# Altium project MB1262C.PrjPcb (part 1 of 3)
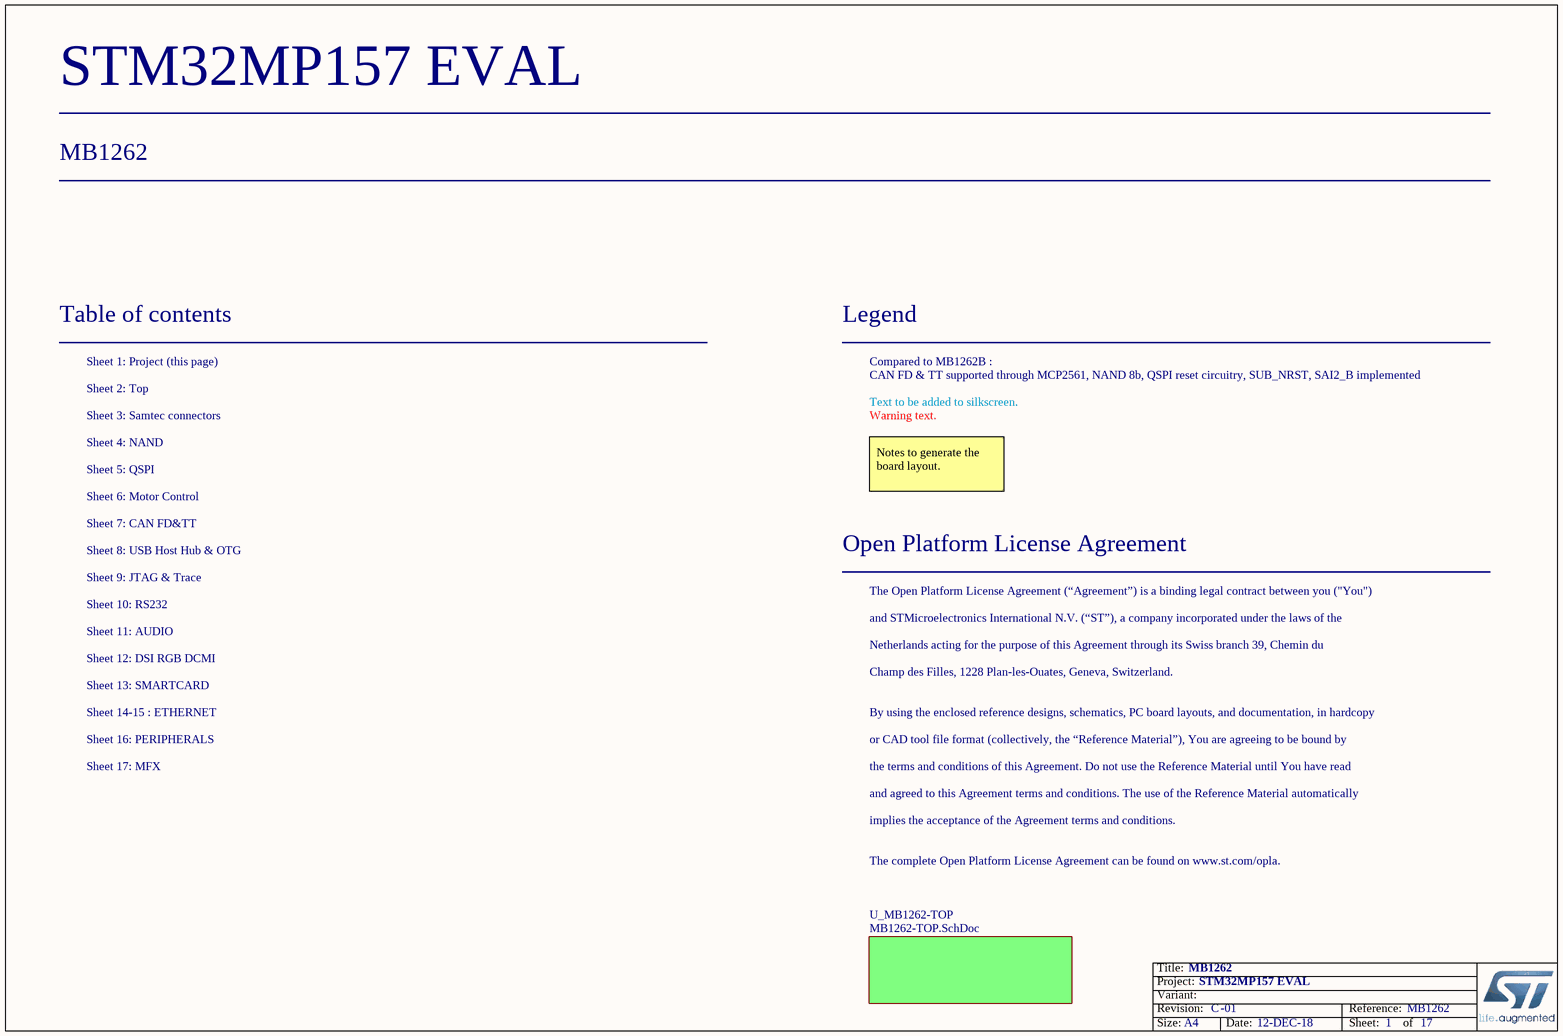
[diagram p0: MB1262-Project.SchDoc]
Board_Reference: MB1262; Board_PCB_Revision: C; Board_Name: STM32MP157 EVAL; Board_Document_Date: 12-DEC-18; Board_Assembly_Revision: 01
17 sheets, 493 parts. Net scope: hierarchical (ports join the sheet entries above them; power ports are global).
Board file: MB1262C.PcbDoc
Sheets:
  MB1262-Project.SchDoc
    U_MB1262-TOP = MB1262-TOP.SchDoc
      U_NAND = NAND.SchDoc
      U_Audio = Audio.SchDoc
      U_Ethernet = Ethernet.SchDoc
        U_Ethernet_connector = Ethernet_connector.SchDoc
      U_DSI&TFT-LCD&Camera = DSI&TFT-LCD&Camera.SchDoc
      U_Peripherals = Peripherals.SchDoc
      U_RS232 = RS232.SchDoc
      U_MotorControl = MotorControl.SchDoc
      U_CAN_FD&TT = CAN_FD&TT.SchDoc
      U_JTAG&Trace = JTAG&Trace.SchDoc
      U_QSPI = QSPI.SchDoc
      U_MFX = MFX.SchDoc
      U_Samtec Connectors QSH_North_South = Samtec Connectors QSH_North_South.SchDoc
      U_SmartCard = SmartCard.SchDoc
      U_USB_Host_Hub&OTG = USB_Host_Hub&OTG.SchDoc

## Sheet MB1262-Project.SchDoc: MB1262
size A4; Date: Not used; ApprovedBy: Not used; CheckedBy: Not used; Author: Not used; CompanyName: STMicroelectronics; DrawnBy: Not used; Engineer: Not used; Organization: Not used; Address1: Not used; Address2: Not used; Address3: Not used; Address4: Not used; DocumentNumber: Not used; Revision: Not used; SheetNumber: 1; SheetTotal: 17

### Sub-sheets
U_MB1262-TOP = MB1262-TOP.SchDoc: no entries

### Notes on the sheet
- Table of contents
- Sheet 1: Project (this page)
- Legend
- Compared to MB1262B :
- CAN FD & TT supported through MCP2561, NAND 8b, QSPI reset circuitry, SUB_NRST, SAI2_B implemented
- Sheet 2: Top
- Sheet 3: Samtec connectors
- Sheet 4: NAND
- Text to be added to silkscreen.
- Warning text.
- Sheet 6: Motor Control
- Sheet 5: QSPI
- Notes to generate the board layout.
- Sheet 7: CAN FD&TT
- Sheet 9: JTAG & Trace
- Sheet 8: USB Host Hub & OTG
- Open Platform License Agreement
- Sheet 10: RS232
- Sheet 11: AUDIO
- The Open Platform License Agreement (“Agreement”) is a binding legal contract between you ("You")
- and STMicroelectronics International N.V. (“ST”), a company incorporated under the laws of the
- Netherlands acting for the purpose of this Agreement through its Swiss branch 39, Chemin du
- Sheet 12: DSI RGB DCMI
- Sheet 13: SMARTCARD
- Sheet 14-15 : ETHERNET
- Champ des Filles, 1228 Plan-les-Ouates, Geneva, Switzerland.
- By using the enclosed reference designs, schematics, PC board layouts, and documentation, in hardcopy
- Sheet 16: PERIPHERALS
- Sheet 17: MFX
- or CAD tool file format (collectively, the “Reference Material”), You are agreeing to be bound by
- the terms and conditions of this Agreement. Do not use the Reference Material until You have read
- and agreed to this Agreement terms and conditions. The use of the Reference Material automatically
- implies the acceptance of the Agreement terms and conditions.
- The complete Open Platform License Agreement can be found on www.st.com/opla.

## Sheet MB1262-TOP.SchDoc: MB1262-TOP
size A3; DocumentNumber: MB1262; Revision: C-01; SheetNumber: 2; SheetTotal: 17; Project: STM32MP15x-EVAL; PageSetup: Record=PageOptions¦CenterHorizontal=True¦CenterVertical=True¦PrintScale=1.01¦XCorrection=1.00¦YCorrection=1.00¦PrintKind=1¦BorderSize=5000000¦LeftOffset=0¦BottomOffset=0¦Orientation=2¦PaperLength=1000¦PaperWidth=1000¦Scale=100¦PaperSource=15¦PrintQuality=600¦MediaType=1¦DitherType=10¦PrintScaleMode=1¦PaperKind=A3¦PaperIndex=8
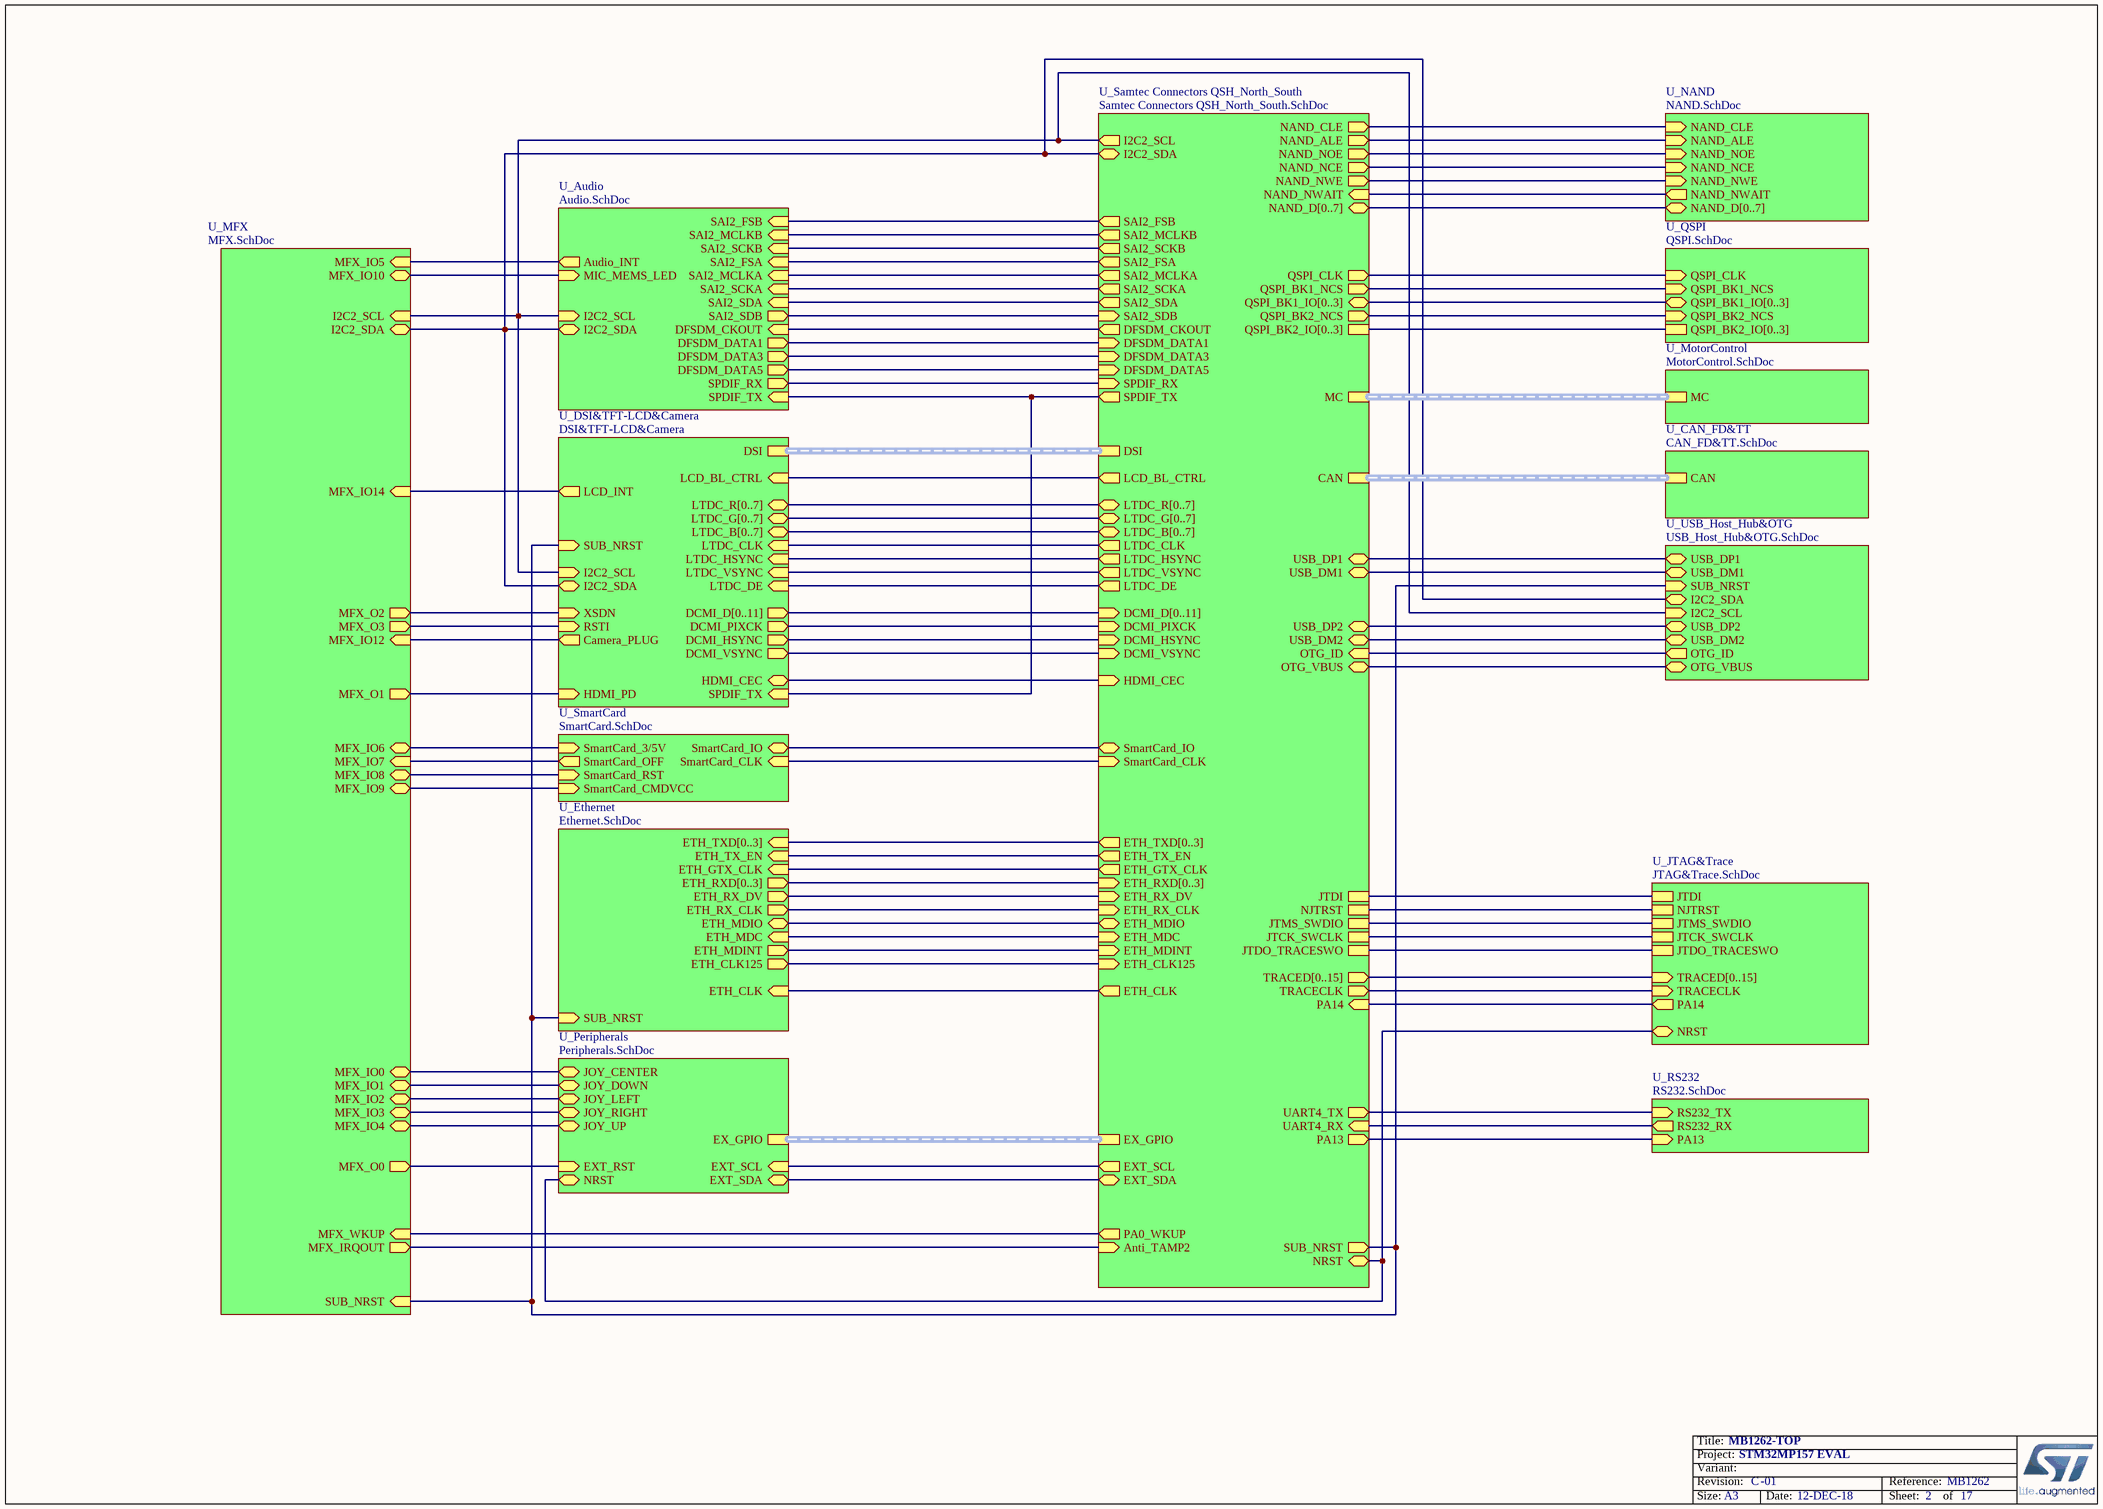
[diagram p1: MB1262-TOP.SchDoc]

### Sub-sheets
U_Audio = Audio.SchDoc: SAI2_SCKA (in), SAI2_FSA (in), SAI2_SDA (in), SAI2_SDB (out), Audio_INT (out), I2C2_SDA (bidir), I2C2_SCL (in), SAI2_MCLKA (in), DFSDM_CKOUT (in), SPDIF_RX (out), SPDIF_TX (in), DFSDM_DATA3 (out), DFSDM_DATA1 (out), DFSDM_DATA5 (out), MIC_MEMS_LED (in), SAI2_MCLKB (in), SAI2_FSB (in), SAI2_SCKB (in)
U_CAN_FD&TT = CAN_FD&TT.SchDoc: CAN (harness CAN)
U_DSI&TFT-LCD&Camera = DSI&TFT-LCD&Camera: LTDC_R[0..7] (bidir), LTDC_HSYNC (in), LTDC_VSYNC (in), LTDC_CLK (in), LTDC_B[0..7] (bidir), LTDC_G[0..7] (bidir), RSTI (in), XSDN (in), DCMI_HSYNC (out), DCMI_PIXCK (out), DCMI_VSYNC (out), Camera_PLUG (out), LCD_INT (out), LCD_BL_CTRL (in), DSI (harness DSI), HDMI_CEC (bidir), LTDC_DE (in), SUB_NRST (in), SPDIF_TX (in), DCMI_D[0..11] (out), I2C2_SDA (bidir), I2C2_SCL (in), HDMI_PD (in)
U_Ethernet = Ethernet.SchDoc: ETH_TXD[0..3] (in), ETH_TX_EN (in), ETH_GTX_CLK (in), ETH_RXD[0..3] (out), ETH_RX_DV (out), ETH_RX_CLK (out), ETH_MDIO (bidir), ETH_MDC (in), ETH_MDINT (out), ETH_CLK125 (out), SUB_NRST (in), ETH_CLK (in)
U_JTAG&Trace = JTAG&Trace.SchDoc: JTDI, NRST (bidir), TRACECLK (in), NJTRST, JTMS_SWDIO, JTCK_SWCLK, JTDO_TRACESWO, PA14 (out), TRACED[0..15] (in)
U_MFX = MFX.SchDoc: MFX_IRQOUT (out), I2C2_SCL (in), I2C2_SDA (bidir), MFX_IO5 (in), MFX_IO6 (bidir), MFX_IO7 (in), MFX_IO8 (bidir), MFX_IO9 (bidir), MFX_IO10 (bidir), MFX_IO12 (in), MFX_IO14 (in), MFX_WKUP (in), MFX_IO0 (bidir), MFX_IO1 (bidir), MFX_IO2 (bidir), MFX_IO3 (bidir), MFX_IO4 (bidir), SUB_NRST (in), MFX_O2 (out), MFX_O0 (out), MFX_O3 (out), MFX_O1 (out)
U_MotorControl = MotorControl.SchDoc: MC (harness Motor Control)
U_NAND = NAND.SchDoc: NAND_CLE (in), NAND_ALE (in), NAND_NOE (in), NAND_NCE (in), NAND_NWE (in), NAND_NWAIT (out), NAND_D[0..7] (bidir)
U_Peripherals = Peripherals.SchDoc: NRST (bidir), JOY_CENTER (bidir), JOY_DOWN (bidir), JOY_LEFT (bidir), JOY_RIGHT (bidir), JOY_UP (bidir), EXT_SCL (in), EXT_SDA (bidir), EXT_RST (in), EX_GPIO (harness EXP_GPIO)
U_QSPI = QSPI.SchDoc: QSPI_BK1_NCS (in), QSPI_CLK (in), QSPI_BK1_IO[0..3] (bidir), QSPI_BK2_NCS (in), QSPI_BK2_IO[0..3]
U_RS232 = RS232.SchDoc: RS232_TX (in), RS232_RX (out), PA13 (in)
U_Samtec Connectors QSH_North_South = Samtec Connectors QSH_North_South.SchDoc: HDMI_CEC (in), DSI (harness DSI), SPDIF_RX (in), JTMS_SWDIO, Anti_TAMP2 (in), SPDIF_TX (out), LCD_BL_CTRL (out), UART4_TX (out), UART4_RX (in), USB_DM2 (bidir), USB_DP2 (bidir), USB_DP1 (bidir), USB_DM1 (bidir), OTG_ID (in), OTG_VBUS (bidir), SAI2_MCLKA (out), SAI2_SCKA (out), SAI2_FSA (out), SAI2_SDA (out), SAI2_SDB (in), DFSDM_CKOUT (out), DFSDM_DATA1 (in), DFSDM_DATA3 (in), QSPI_CLK (out), QSPI_BK1_NCS (out), QSPI_BK1_IO[0..3] (bidir), QSPI_BK2_NCS (out), QSPI_BK2_IO[0..3], ETH_RXD[0..3] (in), ETH_RX_DV (in), ETH_TX_EN (out), ETH_GTX_CLK (out), ETH_RX_CLK (in), ETH_MDIO (bidir), ETH_MDC (in), ETH_TXD[0..3] (out), ETH_CLK125 (in), ETH_MDINT (in), SmartCard_IO (bidir), SmartCard_CLK (in), NAND_CLE (out), NAND_ALE (out), NAND_NCE (out), NAND_NOE (out), NAND_NWE (out), NAND_NWAIT (in), NAND_D[0..7] (bidir), LTDC_R[0..7] (bidir), LTDC_G[0..7] (bidir), LTDC_B[0..7] (bidir), LTDC_HSYNC (out), LTDC_VSYNC (out), LTDC_CLK (out), LTDC_DE (out), DCMI_D[0..11] (in), DCMI_VSYNC (in), DCMI_HSYNC (in), DCMI_PIXCK (in), EX_GPIO (harness EXP_GPIO), I2C2_SCL (out), I2C2_SDA (bidir), EXT_SDA (bidir), EXT_SCL (out), MC (harness Motor Control), JTCK_SWCLK, JTDI, NJTRST, JTDO_TRACESWO, NRST (bidir), PA0_WKUP (out), CAN (harness CAN), PA13 (out), PA14 (in), ETH_CLK (out), TRACED[0..15] (out), TRACECLK (out), DFSDM_DATA5 (in), SAI2_MCLKB (out), SUB_NRST (out), SAI2_SCKB (out), SAI2_FSB (out)
U_SmartCard = SmartCard.SchDoc: SmartCard_3/5V (in), SmartCard_IO (bidir), SmartCard_RST (in), SmartCard_CLK (in), SmartCard_OFF (out), SmartCard_CMDVCC (in)
U_USB_Host_Hub&OTG = USB_Host_Hub&OTG.SchDoc: USB_DP1 (bidir), USB_DM1 (bidir), SUB_NRST (in), I2C2_SDA (bidir), I2C2_SCL (in), USB_DM2 (bidir), USB_DP2 (bidir), OTG_ID (out), OTG_VBUS (bidir)

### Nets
Anti_TAMP2: sheet U_MFX/MFX_IRQOUT, sheet U_Samtec Connectors QSH_North_South/Anti_TAMP2
CLK125: sheet U_Ethernet/ETH_CLK125, sheet U_Samtec Connectors QSH_North_South/ETH_CLK125
DCMI_HSYNC: sheet U_DSI&TFT-LCD&Camera/DCMI_HSYNC, sheet U_Samtec Connectors QSH_North_South/DCMI_HSYNC
DCMI_PIXCK: sheet U_DSI&TFT-LCD&Camera/DCMI_PIXCK, sheet U_Samtec Connectors QSH_North_South/DCMI_PIXCK
DCMI_VSYNC: sheet U_DSI&TFT-LCD&Camera/DCMI_VSYNC, sheet U_Samtec Connectors QSH_North_South/DCMI_VSYNC
DFSDM_CKOUT: sheet U_Audio/DFSDM_CKOUT, sheet U_Samtec Connectors QSH_North_South/DFSDM_CKOUT
DFSDM_DATA1: sheet U_Audio/DFSDM_DATA1, sheet U_Samtec Connectors QSH_North_South/DFSDM_DATA1
DFSDM_DATA3: sheet U_Audio/DFSDM_DATA3, sheet U_Samtec Connectors QSH_North_South/DFSDM_DATA3
DFSDM_DATA5: sheet U_Audio/DFSDM_DATA5, sheet U_Samtec Connectors QSH_North_South/DFSDM_DATA5
ETH_GTX_CLK: sheet U_Ethernet/ETH_GTX_CLK, sheet U_Samtec Connectors QSH_North_South/ETH_GTX_CLK
ETH_MDC: sheet U_Ethernet/ETH_MDC, sheet U_Samtec Connectors QSH_North_South/ETH_MDC
ETH_MDINT: sheet U_Ethernet/ETH_MDINT, sheet U_Samtec Connectors QSH_North_South/ETH_MDINT
ETH_MDIO: sheet U_Ethernet/ETH_MDIO, sheet U_Samtec Connectors QSH_North_South/ETH_MDIO
ETH_RX_CLK: sheet U_Ethernet/ETH_RX_CLK, sheet U_Samtec Connectors QSH_North_South/ETH_RX_CLK
ETH_RX_DV: sheet U_Ethernet/ETH_RX_DV, sheet U_Samtec Connectors QSH_North_South/ETH_RX_DV
ETH_TX_EN: sheet U_Ethernet/ETH_TX_EN, sheet U_Samtec Connectors QSH_North_South/ETH_TX_EN
HDMI_CEC: sheet U_DSI&TFT-LCD&Camera/HDMI_CEC, sheet U_Samtec Connectors QSH_North_South/HDMI_CEC
HDMI_PD: sheet U_DSI&TFT-LCD&Camera/HDMI_PD, sheet U_MFX/MFX_O1
I2C2_SCL: sheet U_Audio/I2C2_SCL, sheet U_DSI&TFT-LCD&Camera/I2C2_SCL, sheet U_MFX/I2C2_SCL, sheet U_Samtec Connectors QSH_North_South/I2C2_SCL, sheet U_USB_Host_Hub&OTG/I2C2_SCL
I2C2_SDA: sheet U_Audio/I2C2_SDA, sheet U_DSI&TFT-LCD&Camera/I2C2_SDA, sheet U_MFX/I2C2_SDA, sheet U_Samtec Connectors QSH_North_South/I2C2_SDA, sheet U_USB_Host_Hub&OTG/I2C2_SDA
JTCK_SWCLK: sheet U_JTAG&Trace/JTCK_SWCLK, sheet U_Samtec Connectors QSH_North_South/JTCK_SWCLK
JTDI: sheet U_JTAG&Trace/JTDI, sheet U_Samtec Connectors QSH_North_South/JTDI
JTDO_TRACESWO: sheet U_JTAG&Trace/JTDO_TRACESWO, sheet U_Samtec Connectors QSH_North_South/JTDO_TRACESWO
JTMS_SWDIO: sheet U_JTAG&Trace/JTMS_SWDIO, sheet U_Samtec Connectors QSH_North_South/JTMS_SWDIO
LCD_BL_CTRL: sheet U_DSI&TFT-LCD&Camera/LCD_BL_CTRL, sheet U_Samtec Connectors QSH_North_South/LCD_BL_CTRL
LCD_INT: sheet U_DSI&TFT-LCD&Camera/LCD_INT, sheet U_MFX/MFX_IO14
LTDC_CLK: sheet U_DSI&TFT-LCD&Camera/LTDC_CLK, sheet U_Samtec Connectors QSH_North_South/LTDC_CLK
LTDC_DE: sheet U_DSI&TFT-LCD&Camera/LTDC_DE, sheet U_Samtec Connectors QSH_North_South/LTDC_DE
LTDC_HSYNC: sheet U_DSI&TFT-LCD&Camera/LTDC_HSYNC, sheet U_Samtec Connectors QSH_North_South/LTDC_HSYNC
LTDC_VSYNC: sheet U_DSI&TFT-LCD&Camera/LTDC_VSYNC, sheet U_Samtec Connectors QSH_North_South/LTDC_VSYNC
MIC_MEMS_LED: sheet U_Audio/MIC_MEMS_LED, sheet U_MFX/MFX_IO10
NAND_ALE: sheet U_NAND/NAND_ALE, sheet U_Samtec Connectors QSH_North_South/NAND_ALE
NAND_CLE: sheet U_NAND/NAND_CLE, sheet U_Samtec Connectors QSH_North_South/NAND_CLE
NAND_NCE: sheet U_NAND/NAND_NCE, sheet U_Samtec Connectors QSH_North_South/NAND_NCE
NAND_NOE: sheet U_NAND/NAND_NOE, sheet U_Samtec Connectors QSH_North_South/NAND_NOE
NAND_NWAIT: sheet U_NAND/NAND_NWAIT, sheet U_Samtec Connectors QSH_North_South/NAND_NWAIT
NAND_NWE: sheet U_NAND/NAND_NWE, sheet U_Samtec Connectors QSH_North_South/NAND_NWE
NJTRST: sheet U_JTAG&Trace/NJTRST, sheet U_Samtec Connectors QSH_North_South/NJTRST
NRST: sheet U_Peripherals/NRST, sheet U_JTAG&Trace/NRST, sheet U_Samtec Connectors QSH_North_South/NRST
OTG_ID: sheet U_Samtec Connectors QSH_North_South/OTG_ID, sheet U_USB_Host_Hub&OTG/OTG_ID
OTG_VBUS: sheet U_Samtec Connectors QSH_North_South/OTG_VBUS, sheet U_USB_Host_Hub&OTG/OTG_VBUS
PA0_WKUP: sheet U_MFX/MFX_WKUP, sheet U_Samtec Connectors QSH_North_South/PA0_WKUP
PA13: sheet U_RS232/PA13, sheet U_Samtec Connectors QSH_North_South/PA13
PA14: sheet U_JTAG&Trace/PA14, sheet U_Samtec Connectors QSH_North_South/PA14
QSPI_BK1_NCS: sheet U_QSPI/QSPI_BK1_NCS, sheet U_Samtec Connectors QSH_North_South/QSPI_BK1_NCS
QSPI_BK2_NCS: sheet U_QSPI/QSPI_BK2_NCS, sheet U_Samtec Connectors QSH_North_South/QSPI_BK2_NCS
QSPI_CLK: sheet U_QSPI/QSPI_CLK, sheet U_Samtec Connectors QSH_North_South/QSPI_CLK
SAI2_FSB: sheet U_Audio/SAI2_FSB, sheet U_Samtec Connectors QSH_North_South/SAI2_FSB
SAI2_MCLKB: sheet U_Audio/SAI2_MCLKB, sheet U_Samtec Connectors QSH_North_South/SAI2_MCLKB
SAI4_SD_A: sheet U_Audio/SPDIF_TX, sheet U_DSI&TFT-LCD&Camera/SPDIF_TX, sheet U_Samtec Connectors QSH_North_South/SPDIF_TX
SmartCard_CLK: sheet U_Samtec Connectors QSH_North_South/SmartCard_CLK, sheet U_SmartCard/SmartCard_CLK
SmartCard_IO: sheet U_Samtec Connectors QSH_North_South/SmartCard_IO, sheet U_SmartCard/SmartCard_IO
SPDIF_RX: sheet U_Audio/SPDIF_RX, sheet U_Samtec Connectors QSH_North_South/SPDIF_RX
UART4_RX: sheet U_RS232/RS232_RX, sheet U_Samtec Connectors QSH_North_South/UART4_RX
UART4_TX: sheet U_RS232/RS232_TX, sheet U_Samtec Connectors QSH_North_South/UART4_TX
USB_AB_N: sheet U_Samtec Connectors QSH_North_South/USB_DM2, sheet U_USB_Host_Hub&OTG/USB_DM2
USB_AB_P: sheet U_Samtec Connectors QSH_North_South/USB_DP2, sheet U_USB_Host_Hub&OTG/USB_DP2
USB_HUB_N: sheet U_Samtec Connectors QSH_North_South/USB_DM1, sheet U_USB_Host_Hub&OTG/USB_DM1
USB_HUB_P: sheet U_Samtec Connectors QSH_North_South/USB_DP1, sheet U_USB_Host_Hub&OTG/USB_DP1
NetC74_2: sheet U_Peripherals/JOY_CENTER, sheet U_MFX/MFX_IO0
NetCN7_15: sheet U_DSI&TFT-LCD&Camera/Camera_PLUG, sheet U_MFX/MFX_IO12
NetCN7_17: sheet U_DSI&TFT-LCD&Camera/RSTI, sheet U_MFX/MFX_O3
NetCN7_19: sheet U_DSI&TFT-LCD&Camera/XSDN, sheet U_MFX/MFX_O2
NetCN10_26: sheet U_Ethernet/SUB_NRST, sheet U_DSI&TFT-LCD&Camera/SUB_NRST, sheet U_MFX/SUB_NRST, sheet U_Samtec Connectors QSH_North_South/SUB_NRST, sheet U_USB_Host_Hub&OTG/SUB_NRST
NetCN13_1: sheet U_Peripherals/EXT_SDA, sheet U_Samtec Connectors QSH_North_South/EXT_SDA
NetCN13_3: sheet U_Peripherals/EXT_SCL, sheet U_Samtec Connectors QSH_North_South/EXT_SCL
NetCN13_4: sheet U_Peripherals/EXT_RST, sheet U_MFX/MFX_O0
NetR5_2: sheet U_MFX/MFX_IO6, sheet U_SmartCard/SmartCard_3/5V
NetR22_1: sheet U_MFX/MFX_IO9, sheet U_SmartCard/SmartCard_CMDVCC
NetR23_1: sheet U_MFX/MFX_IO8, sheet U_SmartCard/SmartCard_RST
NetR24_2: sheet U_MFX/MFX_IO7, sheet U_SmartCard/SmartCard_OFF
NetR54_1: sheet U_Audio/SAI2_FSA, sheet U_Samtec Connectors QSH_North_South/SAI2_FSA
NetR77_1: sheet U_Ethernet/ETH_CLK, sheet U_Samtec Connectors QSH_North_South/ETH_CLK
NetR103_1: sheet U_Peripherals/JOY_LEFT, sheet U_MFX/MFX_IO2
NetR104_1: sheet U_Peripherals/JOY_DOWN, sheet U_MFX/MFX_IO1
NetR122_1: sheet U_Peripherals/JOY_RIGHT, sheet U_MFX/MFX_IO3
NetR123_1: sheet U_Peripherals/JOY_UP, sheet U_MFX/MFX_IO4
NetSB4_1: sheet U_Audio/SAI2_SDB, sheet U_Samtec Connectors QSH_North_South/SAI2_SDB
NetSB6_2: sheet U_Audio/SAI2_SCKB, sheet U_Samtec Connectors QSH_North_South/SAI2_SCKB
NetSB7_2: sheet U_Audio/SAI2_MCLKA, sheet U_Samtec Connectors QSH_North_South/SAI2_MCLKA
NetSB9_2: sheet U_Audio/SAI2_SCKA, sheet U_Samtec Connectors QSH_North_South/SAI2_SCKA
NetSB10_2: sheet U_Audio/SAI2_SDA, sheet U_Samtec Connectors QSH_North_South/SAI2_SDA
NetSB38_2: sheet U_JTAG&Trace/TRACECLK, sheet U_Samtec Connectors QSH_North_South/TRACECLK
NetU8_G3: sheet U_Audio/Audio_INT, sheet U_MFX/MFX_IO5

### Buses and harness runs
bus sheet U_DSI&TFT-LCD&Camera/DCMI_D[0..11] = sheet U_Samtec Connectors QSH_North_South/DCMI_D[0..11]
bus sheet U_DSI&TFT-LCD&Camera/LTDC_B[0..7] = sheet U_Samtec Connectors QSH_North_South/LTDC_B[0..7]
bus sheet U_DSI&TFT-LCD&Camera/LTDC_G[0..7] = sheet U_Samtec Connectors QSH_North_South/LTDC_G[0..7]
bus sheet U_DSI&TFT-LCD&Camera/LTDC_R[0..7] = sheet U_Samtec Connectors QSH_North_South/LTDC_R[0..7]
bus sheet U_Ethernet/ETH_RXD[0..3] = sheet U_Samtec Connectors QSH_North_South/ETH_RXD[0..3]
bus sheet U_Ethernet/ETH_TXD[0..3] = sheet U_Samtec Connectors QSH_North_South/ETH_TXD[0..3]
bus sheet U_JTAG&Trace/TRACED[0..15] = sheet U_Samtec Connectors QSH_North_South/TRACED[0..15]
bus sheet U_NAND/NAND_D[0..7] = sheet U_Samtec Connectors QSH_North_South/NAND_D[0..7]
bus sheet U_QSPI/QSPI_BK1_IO[0..3] = sheet U_Samtec Connectors QSH_North_South/QSPI_BK1_IO[0..3]
bus sheet U_QSPI/QSPI_BK2_IO[0..3] = sheet U_Samtec Connectors QSH_North_South/QSPI_BK2_IO[0..3]
harness sheet U_CAN_FD&TT/CAN = sheet U_Samtec Connectors QSH_North_South/CAN
harness sheet U_DSI&TFT-LCD&Camera/DSI = sheet U_Samtec Connectors QSH_North_South/DSI
harness sheet U_MotorControl/MC = sheet U_Samtec Connectors QSH_North_South/MC
harness sheet U_Peripherals/EX_GPIO = sheet U_Samtec Connectors QSH_North_South/EX_GPIO

## Sheet NAND.SchDoc: NAND Flash
size A4; CompanyName: STMicroelectronics; DocumentNumber: MB1262; Revision: C-01; SheetNumber: 4; SheetTotal: 17; Project: STM32MP15x-EVAL
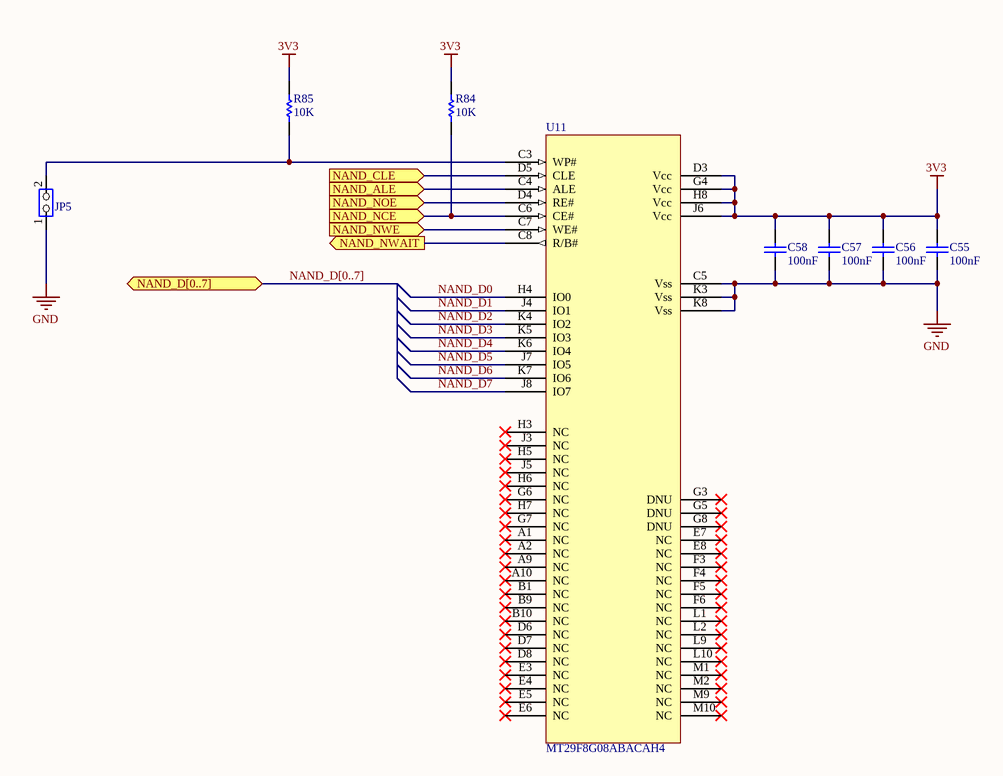
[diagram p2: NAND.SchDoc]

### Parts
C55  100nF  [C0402]
C56  100nF  [C0402]
C57  100nF  [C0402]
C58  100nF  [C0402]
JP5  Jumper_2.54mm  [CON_SAMTEC_TSW-102-07-G-S]  (value not drawn)
R84  10K  [R0402]
R85  10K  [R0402]
U11  MT29F8G08ABACAH4  [ICC_VFBGA63_9X11_P080]

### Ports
NAND_ALE (in), NAND_CLE (in), NAND_D[0..7] (bidir), NAND_NCE (in), NAND_NOE (in), NAND_NWAIT (out), NAND_NWE (in)

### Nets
3V3: C55.2 C56.2 C57.2 C58.2 R84.2 R85.2 U11.D3(Vcc) U11.G4(Vcc) U11.H8(Vcc) U11.J6(Vcc)
GND: C55.1 C56.1 C57.1 C58.1 JP5.1(COMMON) U11.C5(Vss) U11.K3(Vss) U11.K8(Vss)
NAND_ALE: U11.C4(ALE) ; port NAND_ALE
NAND_CLE: U11.D5(CLE) ; port NAND_CLE
NAND_D0: U11.H4(IO0)
NAND_D1: U11.J4(IO1)
NAND_D2: U11.K4(IO2)
NAND_D3: U11.K5(IO3)
NAND_D4: U11.K6(IO4)
NAND_D5: U11.J7(IO5)
NAND_D6: U11.K7(IO6)
NAND_D7: U11.J8(IO7)
NAND_NCE: R84.1 U11.C6(CE#) ; port NAND_NCE
NAND_NOE: U11.D4(RE#) ; port NAND_NOE
NAND_NWAIT: U11.C8(R/B#) ; port NAND_NWAIT
NAND_NWE: U11.C7(WE#) ; port NAND_NWE
NetJP5_2: JP5.2(NO) R85.1 U11.C3(WP#)

Not connected (* = marked no-connect by the designer): U11 A1(NC)* A2(NC)* A9(NC)* A10(NC)* B1(NC)* B9(NC)* B10(NC)* D6(NC)* D7(NC)* D8(NC)* E3(NC)* E4(NC)* E5(NC)* E6(NC)* E7(NC)* E8(NC)* F3(NC)* F4(NC)* F5(NC)* F6(NC)* G3(DNU)* G5(DNU)* G6(NC)* G7(NC)* G8(DNU)* H3(NC)* H5(NC)* H6(NC)* H7(NC)* J3(NC)* J5(NC)* L1(NC)* L2(NC)* L9(NC)* L10(NC)* M1(NC)* M2(NC)* M9(NC)* M10(NC)*

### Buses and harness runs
bus NAND_D[0..7] = port NAND_D[0..7]

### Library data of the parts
C55-C58 = Cap_100nF_X7R_10%_0402: Capacitor,100nF,16V,X7R,10%,0402,YAGEO; Manuf_Part_1: CC0402KRX7R7BB104; Fitted: YES; Ordered_By: Subcon
JP5 = TSW-102-07-x-S: Connector jumper 1 position; Manuf_1: SAMTEC; Manuf_Part_2: 4711955140470; Manuf_2: KONTEC; Order_Code: 423-2841; Fitted: YES; Ordered_By: Subcon
R84 R85 = Res_10K_1%_0402: Resistor,10K,0402,1%,YAGEO; Manuf_Part_1: RC0402FR-0710KL; Order_Code: 9239359RL; Fitted: YES; Ordered_By: Subcon
U11 = MT29F8G08ABACAH4: SLC NAND 8Gb/8bits/8ECC/4K VFBGA 9x11; Manuf_Part_1: MT29F8G08ABACAH4-ITS:C; Manuf_1: MICRON; Ordered_By: STM

## Sheet Audio.SchDoc: Audio
size A3; DocumentNumber: MB1262; Revision: C-01; SheetNumber: 11; SheetTotal: 17; Project: STM32MP15x-EVAL
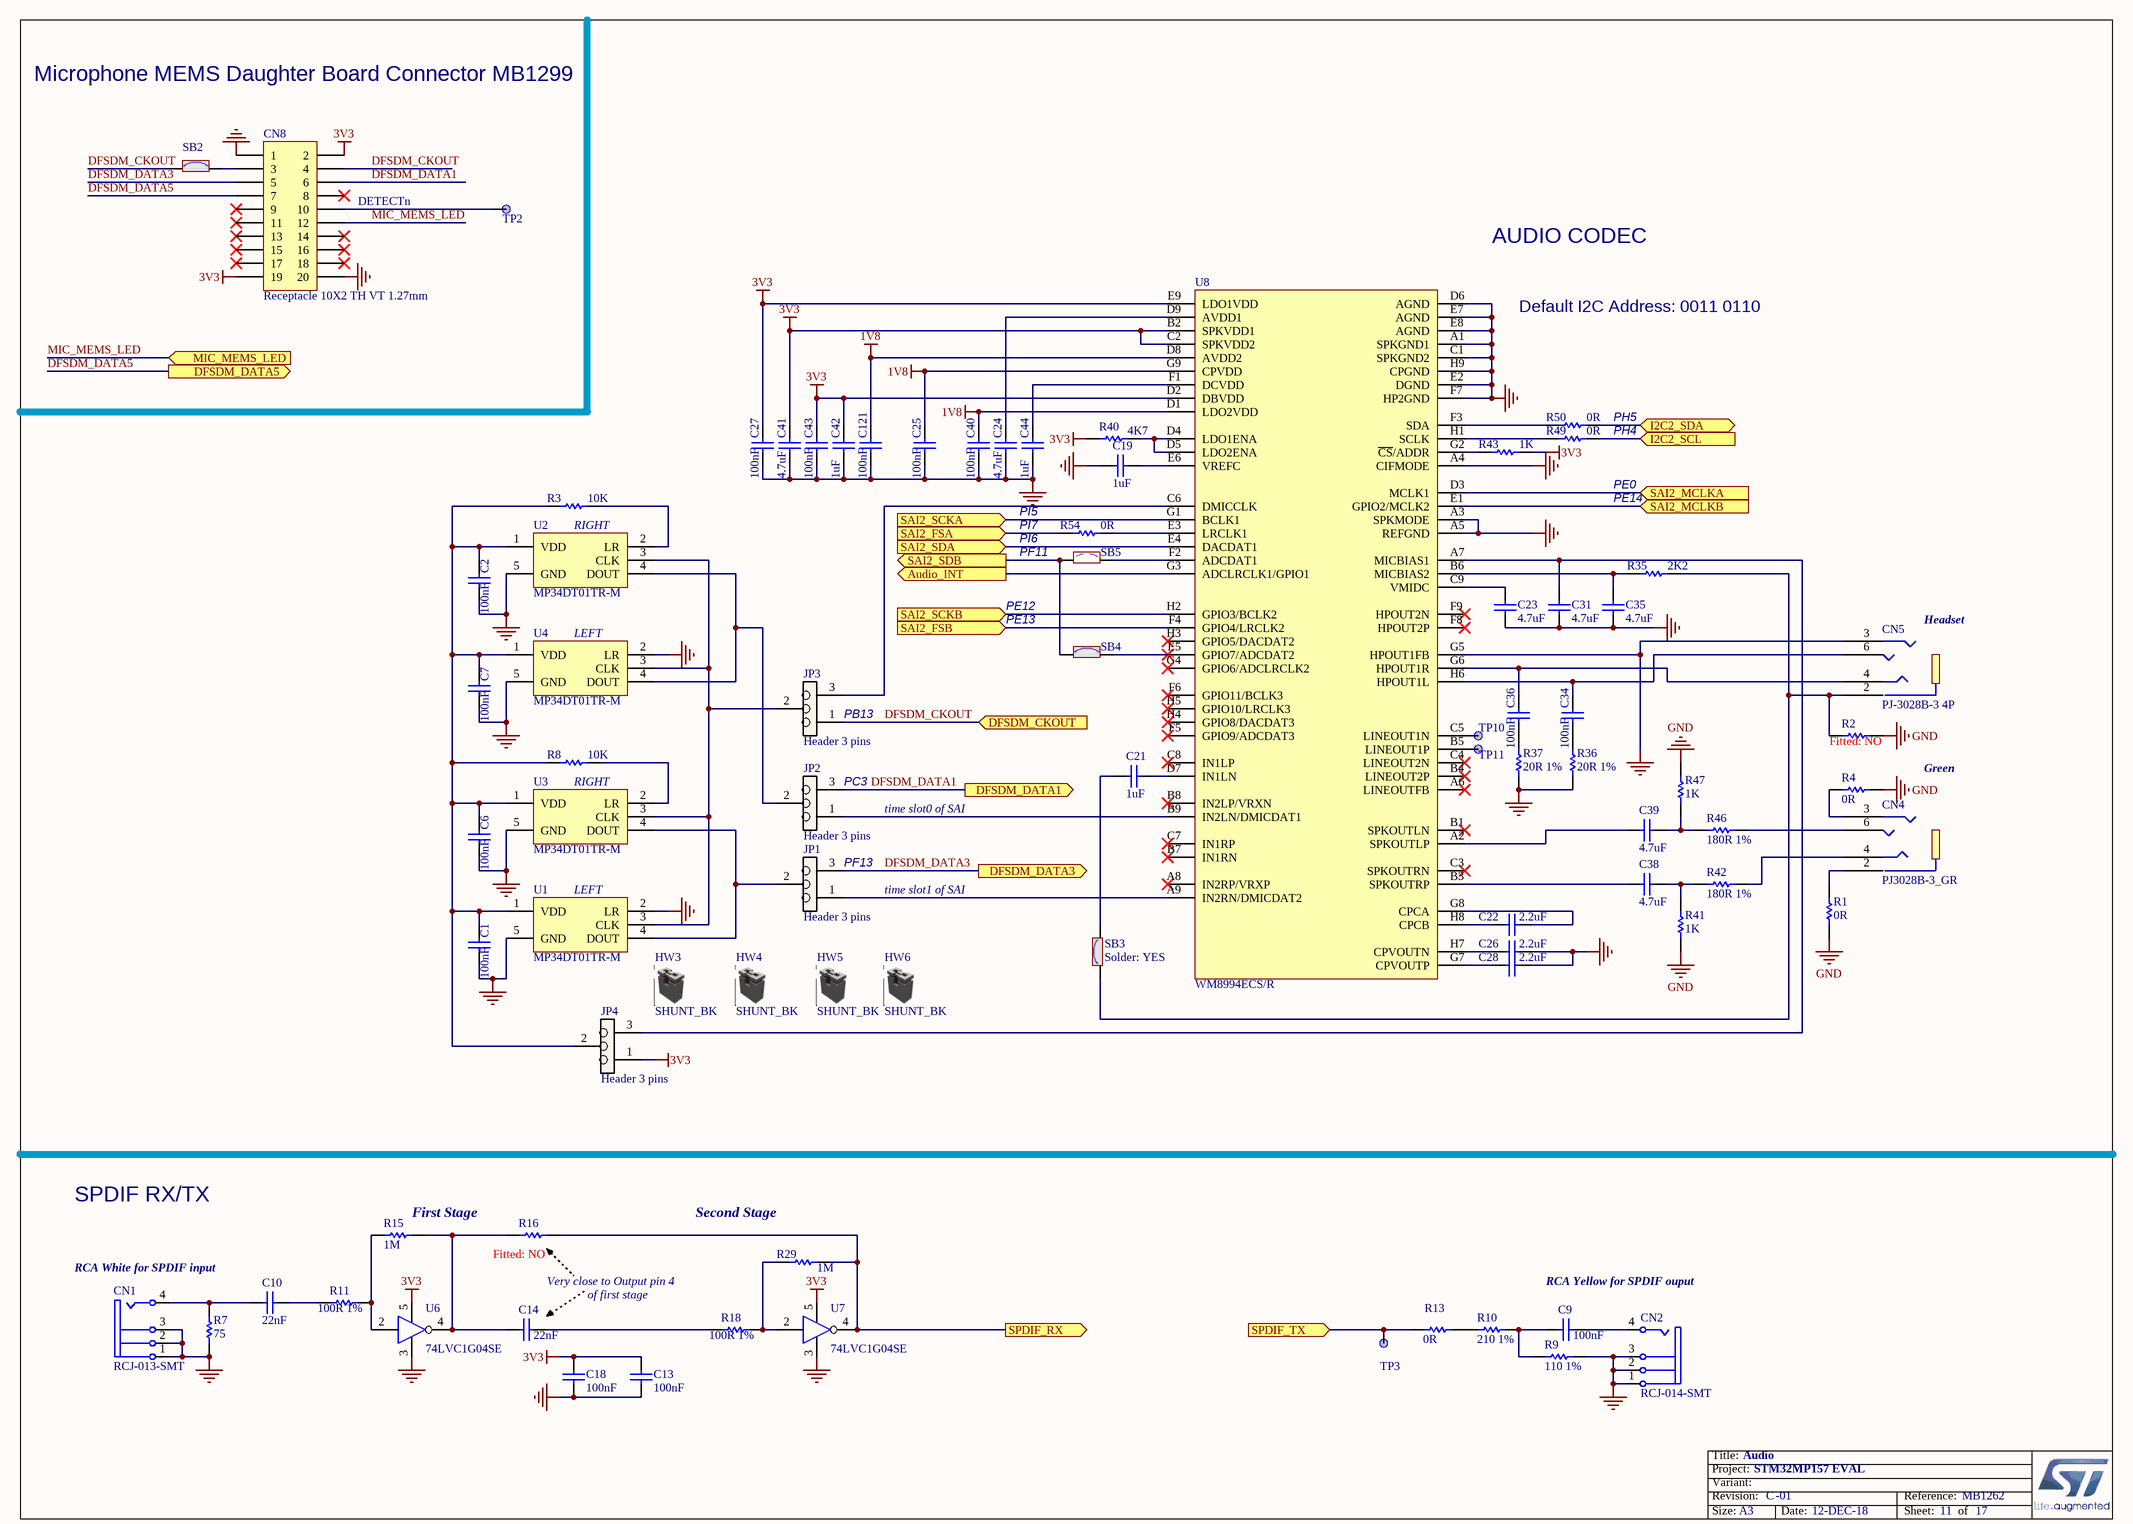
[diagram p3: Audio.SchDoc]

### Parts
C1  100nF  [C0402]
C2  100nF  [C0402]
C6  100nF  [C0402]
C7  100nF  [C0402]
C9  100nF  [C0402]
C10  22nF  [C0402]
C13  100nF  [C0402]
C14  22nF  [C0402]
C18  100nF  [C0402]
C19  1uF  [C0402]
C21  1uF  [C0402]
C22  2.2uF  [C0603]
C23  4.7uF  [C0402]
C24  4.7uF  [C0402]
C25  100nF  [C0402]
C26  2.2uF  [C0603]
C27  100nF  [C0402]
C28  2.2uF  [C0603]
C31  4.7uF  [C0402]
C34  100nF  [C0402]
C35  4.7uF  [C0402]
C36  100nF  [C0402]
C38  4.7uF  [C0402]
C39  4.7uF  [C0402]
C40  100nF  [C0402]
C41  4.7uF  [C0402]
C42  1uF  [C0402]
C43  100nF  [C0402]
C44  1uF  [C0402]
C121  100nF  [C0402]
CN1  RCJ-013-SMT  [CON_SMD-RCA-SOCKET_CUI_RCJ-013-SMT]
CN2  RCJ-014-SMT  [CON_SMD-RCA-SOCKET_CUI_RCJ-013-SMT]
CN4  PJ3028B-3_GR  [CON_PHONE-JACK-3P5_HY_PJ3028B]
CN5  PJ-3028B-3 4P  [CON_PHONE-JACK-3P5_HY_PJ3028B]
CN8  Receptacle 10X2 TH VT 1.27mm  [CON_FCI_20021311-XXX20XXLF_MOD-MB1299]
HW3  SHUNT_BK  (mechanical)
HW4  SHUNT_BK  (mechanical)
HW5  SHUNT_BK  (mechanical)
HW6  SHUNT_BK  (mechanical)
JP1  Header 3 pins  [CON_SAMTEC_TSW-103-07-F-S]
JP2  Header 3 pins  [CON_SAMTEC_TSW-103-07-F-S]
JP3  Header 3 pins  [CON_SAMTEC_TSW-103-07-F-S]
JP4  Header 3 pins  [CON_SAMTEC_TSW-103-07-F-S]
R1  0R  [R0402]
R2  Fitted: NO  [R0402]  (hidden comment: 1K)
R3  10K  [R0402]
R4  0R  [R0402]
R7  75  [R0402]
R8  10K  [R0402]
R9  110 1%  [R0402]
R10  210 1%  [R0402]
R11  100R 1%  [R0402]
R13  0R  [R0402]
R15  1M  [R0402]
R16  Fitted: NO  [R0402]  (hidden comment: 0R)
R18  100R 1%  [R0402]
R29  1M  [R0402]
R35  2K2  [R0402]
R36  20R 1%  [R0402]
R37  20R 1%  [R0402]
R40  4K7  [R0402]
R41  1K  [R0402]
R42  180R 1%  [R0402]
R43  1K  [R0402]
R46  180R 1%  [R0402]
R47  1K  [R0402]
R49  0R  [R0402]
R50  0R  [R0402]
R54  0R  [R0402]
SB2  SB_ON  [SOLDER-BRIDGE_R0603-0R]  (value not drawn)
SB3  Solder: YES  [SOLDER-BRIDGE_R0603-0R]  (hidden comment: SB_ON)
SB4  SB_ON  [SOLDER-BRIDGE_R0603-0R]  (value not drawn)
SB5  SB_OFF  [SOLDER-BRIDGE_R0603-0R]  (value not drawn)
TP2  TP  [TP_SMD_1MM]  (value not drawn)
TP3  TP  [TP_SMD_1MM]  (value not drawn)
TP10  TP  [TP_SMD_1MM]  (value not drawn)
TP11  TP  [TP_SMD_1MM]  (value not drawn)
U1  MP34DT01TR-M  [MIC_HCLGA_3X4X1_4LD]
U2  MP34DT01TR-M  [MIC_HCLGA_3X4X1_4LD]
U3  MP34DT01TR-M  [MIC_HCLGA_3X4X1_4LD]
U4  MP34DT01TR-M  [MIC_HCLGA_3X4X1_4LD]
U6  74LVC1G04SE  [DIO_SOT353]
U7  74LVC1G04SE  [DIO_SOT353]
U8  WM8994ECS/R  [ICC_W-CSP-BGA72_4P511X4P023_P050]

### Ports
Audio_INT (out), DFSDM_CKOUT (in), DFSDM_DATA1 (out), DFSDM_DATA3 (out), DFSDM_DATA5 (out), I2C2_SCL (in), I2C2_SDA (bidir), MIC_MEMS_LED (in), SAI2_FSA (in), SAI2_FSB (in), SAI2_MCLKA (in), SAI2_MCLKB (in), SAI2_SCKA (in), SAI2_SCKB (in), SAI2_SDA (in), SAI2_SDB (out), SPDIF_RX (out), SPDIF_TX (in)

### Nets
1V8: C25.2 C40.2 C121.2 U8.D1(LDO2VDD) U8.D8(AVDD2) U8.G9(CPVDD)
3V3: C13.1 C18.1 C27.2 C41.2 C42.2 C43.2 CN8.2 CN8.19 JP4.1 R40.1 R43.2 U6.5(VCC) U7.5(VCC) U8.B2(SPKVDD1) U8.C2(SPKVDD2) U8.D2(DBVDD) U8.E9(LDO1VDD)
GND: C1.1 C2.1 C6.1 C7.1 C13.2 C18.2 C19.2 C23.1 C24.1 C25.1 C26.2 C27.1 C28.2 C31.1 C35.1 C40.1 C41.1 C42.1 C43.1 C44.1 C121.1 CN1.1(Ground) CN1.2(Ground) CN1.3(Ground) CN2.1(Ground) CN2.2(Ground) CN2.3(Ground) CN5.3 CN8.1 CN8.20 R1.1 R2.2 R4.2 R7.1 R9.2 R36.1 R37.1 R41.1 R47.2 U1.2(LR) U1.5(GND) U2.5(GND) U3.5(GND) U4.2(LR) U4.5(GND) U6.3(GND) U7.3(GND) U8.A1(SPKGND1) U8.A3(SPKMODE) U8.A4(CIFMODE) U8.A5(REFGND) U8.C1(SPKGND2) U8.D6(AGND) U8.E2(DGND) U8.E7(AGND) U8.E8(AGND) U8.F7(HP2GND) U8.G5(HPOUT1FB) U8.H9(CPGND)
DFSDM_CKOUT: CN8.4 JP3.1 SB2.1 ; port DFSDM_CKOUT
DFSDM_DATA1: CN8.6 JP2.3 ; port DFSDM_DATA1
DFSDM_DATA3: CN8.5 JP1.3 ; port DFSDM_DATA3
DFSDM_DATA5: CN8.7 ; port DFSDM_DATA5
I2C2_SCL: R49.2 ; port I2C2_SCL
I2C2_SDA: R50.2 ; port I2C2_SDA
MIC_MEMS_LED: CN8.12 ; port MIC_MEMS_LED
SAI2_FSB: U8.F4(GPIO4/LRCLK2) ; port SAI2_FSB
SAI2_MCLKB: U8.E1(GPIO2/MCLK2) ; port SAI2_MCLKB
SAI4_SD_A: R13.1 TP3.1 ; port SPDIF_TX
SPDIF_RX: R16.2 R29.2 U7.4(Y) ; port SPDIF_RX
NetC1_2: C1.2 C2.2 C6.2 C7.2 JP4.2 R3.1 R8.1 U1.1(VDD) U2.1(VDD) U3.1(VDD) U4.1(VDD)
NetC9_1: C9.1 CN2.4(Signal)
NetC9_2: C9.2 R9.1 R10.2
NetC10_1: C10.1 CN1.4(Signal) R7.2
NetC10_2: C10.2 R11.1
NetC14_1: C14.1 R15.2 R16.1 U6.4(Y)
NetC14_2: C14.2 R18.1
NetC19_1: C19.1 U8.E6(VREFC)
NetC21_1: C21.1 U8.D7(IN1LN)
NetC21_2: C21.2 SB3.2
NetC22_1: C22.1 U8.H8(CPCB)
NetC22_2: C22.2 U8.G8(CPCA)
NetC23_2: C23.2 U8.C9(VMIDC)
NetC24_2: C24.2 U8.D9(AVDD1)
NetC26_1: C26.1 U8.H7(CPVOUTN)
NetC28_1: C28.1 U8.G7(CPVOUTP)
NetC31_2: C31.2 JP4.3 U8.A7(MICBIAS1)
NetC34_1: C34.1 R36.2
NetC34_2: C34.2 CN5.6 U8.H6(HPOUT1L)
NetC35_2: C35.2 R35.1 U8.B6(MICBIAS2)
NetC36_1: C36.1 R37.2
NetC36_2: C36.2 CN5.4 U8.G6(HPOUT1R)
NetC38_1: C38.1 R41.2 R42.1
NetC38_2: C38.2 U8.B3(SPKOUTRP)
NetC39_1: C39.1 R46.1 R47.1
NetC39_2: C39.2 U8.A2(SPKOUTLP)
NetC44_2: C44.2 U8.F1(DCVDD)
NetCN4_2: CN4.2 R1.2
NetCN4_3: CN4.3 R4.1
NetCN4_4: CN4.4 R42.2
NetCN4_6: CN4.6 R46.2
NetCN5_2: CN5.2 R2.1 R35.2 SB3.1
NetCN8_3: CN8.3 SB2.2
NetCN8_10: CN8.10 TP2.1
NetJP1_1: JP1.1 U8.A9(IN2RN/DMICDAT2)
NetJP1_2: JP1.2 U1.4(DOUT) U3.4(DOUT)
NetJP2_1: JP2.1 U8.B9(IN2LN/DMICDAT1)
NetJP2_2: JP2.2 U2.4(DOUT) U4.4(DOUT)
NetJP3_2: JP3.2 U1.3(CLK) U2.3(CLK) U3.3(CLK) U4.3(CLK)
NetJP3_3: JP3.3 U8.C6(DMICCLK)
NetR3_2: R3.2 U2.2(LR)
NetR8_2: R8.2 U3.2(LR)
NetR10_1: R10.1 R13.2
NetR11_2: R11.2 R15.1 U6.2(A)
NetR18_2: R18.2 R29.1 U7.2(A)
NetR40_2: R40.2 U8.D4(LDO1ENA) U8.D5(LDO2ENA)
NetR43_1: R43.1 U8.G2(~{CS}/ADDR)
NetR49_1: R49.1 U8.H1(SCLK)
NetR50_1: R50.1 U8.F3(SDA)
NetR54_1: R54.1 ; port SAI2_FSA
NetR54_2: R54.2 U8.E3(LRCLK1)
NetSB4_1: SB4.1 SB5.1 ; port SAI2_SDB
NetSB4_2: SB4.2 U8.E5(GPIO7/ADCDAT2)
NetSB5_2: SB5.2 U8.F2(ADCDAT1)
NetSB6_2: U8.H2(GPIO3/BCLK2) ; port SAI2_SCKB
NetSB7_2: U8.D3(MCLK1) ; port SAI2_MCLKA
NetSB9_2: U8.G1(BCLK1) ; port SAI2_SCKA
NetSB10_2: U8.E4(DACDAT1) ; port SAI2_SDA
NetTP10_1: TP10.1 U8.C5(LINEOUT1N)
NetTP11_1: TP11.1 U8.B5(LINEOUT1P)
NetU8_G3: U8.G3(ADCLRCLK1/GPIO1) ; port Audio_INT

Not connected (* = marked no-connect by the designer): CN8 8* 9* 11* 13* 14* 15* 16* 17* 18*; U6 1(NC); U7 1(NC); U8 A6(LINEOUTFB)* A8(IN2RP/VRXP)* B1(SPKOUTLN)* B4(LINEOUT2P)* B7(IN1RN)* B8(IN2LP/VRXN)* C3(SPKOUTRN)* C4(LINEOUT2N)* C7(IN1RP)* C8(IN1LP)* F5(GPIO9/ADCDAT3)* F6(GPIO11/BCLK3)* F8(HPOUT2P)* F9(HPOUT2N)* G4(GPIO6/ADCLRCLK2)* H3(GPIO5/DACDAT2)* H4(GPIO8/DACDAT3)* H5(GPIO10/LRCLK3)*

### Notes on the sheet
- Microphone MEMS Daughter Board Connector MB1299
- (near CN8) DETECTn
- AUDIO CODEC
- Default I2C Address: 0011 0110
- PH5
- PH4
- RIGHT
- PI5
- PI7
- PE0
- PE14
- PI6
- PF11
- (near U4) LEFT
- PE12
- PE13
- (near CN5) Headset
- (near JP3) PB13
- (near JP2) PC3
- Green
- (near JP1) PF13
- time slot0 of SAI
- (near U1) LEFT
- time slot1 of SAI
- SPDIF RX/TX
- RCA White for SPDIF input
- (near R15) First Stage
- (near R29) Second Stage
- Very close to Output pin 4
- of first stage
- RCA Yellow for SPDIF ouput

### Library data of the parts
C1 C2 C6 C7 C9 C13 C18 C25 C27 C34 C36 C40 C43 C121 = Cap_100nF_X7R_10%_0402: as C55 on sheet NAND
C10 C14 = Cap_22nF_X7R_10%_0402: Capacitor,22nF,16V,X7R,10%,0402,YAGEO; Manuf_Part_1: CC0402KRX7R7BB223; Fitted: YES; Ordered_By: Subcon
C19 C21 C42 C44 = Cap_1uF_X5R_10%_6V3_0402: Capacitor MLCC 1µF 10% 6,3V 0,4uF@3,3V X5R 0402 MURATA; Manuf_Part_1: GRM155R61E105KA12; Fitted: YES; Ordered_By: Subcon
C22 C26 C28 = Cap_2.2uF_X5R_10%_0603: Capacitor,2.2uF,10V, X5R,10%,0603,YAGEO; Manuf_Part_1: CC0603KRX5R6BB225; Manuf_Part_2: C0603C225K8PACTU; Manuf_2: KEMET; Fitted: YES; Ordered_By: Subcon
C23 C24 C31 C35 C38 C39 C41 = Cap_4.7uF_X5R_20%_6V3_0402: Capacitor MLCC 4,7µF 20% 6,3V 1,9uF@3,3V X5R 0402; Manuf_Part_1: GRM155R60J475ME87; Manuf_1: MURATA; Fitted: YES; Ordered_By: Subcon
CN1 = RCJ-013-SMT: RCA Phono Jack, Right Angle, SMD, White; Manuf_Part_1: JBB0819100004; Manuf_1: JIUBABA; Manuf_2: CUI Inc; Ordered_By: Subcon; Fitted: YES
CN2 = RCJ-014-SMT: RCA Phono Jack, Right Angle, SMD, Yellow; Manuf_Part_1: JBB0819100002; Manuf_1: JIUBABA; Manuf_2: CUI Inc; Ordered_By: Subcon; Fitted: YES
CN4 = PJ3028B-3_GR: Connector Jack Stereo 3.5mm, female SMT, Green (Line output); Manuf_Part_2: PJ30280-3_GR; Fitted: YES; Ordered_By: Subcon
CN5 = PJ3028B-3_GR: Headset Connector Stereo 3.5mm, female SMT, black; Fitted: YES; Ordered_By: Subcon
CN8 = Header 10X2 TH VT 1.27mm_with MB1299: 20 Position Receptacle Connector 0.050" (1.27mm) Through Hole Vertical Mount; Manuf_1: AMPHEMOL_FCI; Manuf_Part_1: 20021311-00020T4LF; Fitted: YES; Ordered_By: Subcon
HW3-HW6 = Shunt 2.54mm: SHUNT 2.54mm BLACK; Manuf_1: SAMTEC; Manuf_Part_1: SNT-100-BK-G; Fitted: YES; Ordered_By: Subcon
JP1-JP4 = Header 3: Header, 3-Pin; Manuf_1: Samtec; Manuf_Part_1: TSW-103-07-F-S; Fitted: YES; Ordered_By: Subcon
R1 R4 R13 R49 R50 R54 = Res_0_5%_0402: Resistor,0R,0402,5%,YAGEO; Manuf_Part_1: RC0402JR-070RL; Order_Code: 2363467; Fitted: YES; Ordered_By: Subcon
R2 = Res_1K_1%_0402: Resistor,1K,0402,1%,YAGEO; Manuf_Part_1: RC0402FR-071KL; Fitted: NO; Ordered_By: Subcon
R3 R8 = Res_10K_1%_0402: as R84 on sheet NAND
R7 = Res_75_1%_0402: Resistor,75,0402,1%,YAGEO; Manuf_Part_1: RC0402FR-0775RL; Order: 311-75.0LRTR-ND; Ordered_By: Subcon; Fitted: YES
R9 = Res_110_1%_0402: Resistor,110R,0402,1%,YAGEO; Manuf_Part_1: RC0402FR-07110RL; Value: 110; Fitted: YES; Ordered_By: Subcon
R10 = Res_210_1%_0402: Resistor,210R,0402,1%,YAGEO; Manuf_Part_1: RC0402FR-07210RL; Value: 210; Fitted: YES; Ordered_By: Subcon
R11 R18 = Res_100_1%_0402: Resistor,100R,0402,1%,YAGEO; Manuf_Part_1: RC0402FR-07100RL; Order_Code: 9239111; Fitted: YES; Ordered_By: Subcon
R15 = Res_1M_1%_0402: Resistor,1M,0402,1%,YAGEO; Manuf_Part_2: RC0402FR-071ML; Fitted: YES; Ordered_By: Subcon
R16 = Res_0_5%_0402: Resistor,0R,0402,5%,YAGEO; Manuf_Part_1: RC0402JR-070RL; Order_Code: 2363467; Ordered_By: Subcon
R29 = Res_1M_1%_0402: Resistor,1M,0402,1%,YAGEO; Manuf_Part_1: RC0402FR-071ML; Fitted: YES
R35 = Res_2K2_1%_0402: Resistor,2K2,0402,1%,YAGEO; Manuf_Part_1: RC0402FR-072K2L; Fitted: YES; Ordered_By: Subcon
R36 R37 = Res_20_1%_0402: Resistor,20R,0402,1%,YAGEO; Manuf_Part_1: RC0402FR-0720RL; Order_Code: 9239111; Fitted: YES; Ordered_By: Subcon
R40 = Res_4K7_1%_0402: Resistor,4K7,0402,1%,YAGEO; Manuf_Part_2: RT0402FRE074K7L; Manuf_Part_1: RC0402FR-074K7L; Fitted: YES; Ordered_By: Subcon
R41 R47 = Res_1K_1%_0402: Resistor,1K,0402,1%,YAGEO; Manuf_Part_1: RC0402FR-071KL; Fitted: YES; Ordered_By: Subcon
R42 R46 = Res_180_1%_0402_1: Resistor,180R,0402,1%,YAGEO; Manuf_Part_1: RC0402FR-07180RL; Order_Code: 9239146RL; Fitted: YES; Ordered_By: Subcon
R43 = Res_1K_1%_0402: Resistor,1K,0402,1%,YAGEO; Manuf_Part_1: RC0402FR-071KL; Ordered_By: Subcon; Fitted: YES
SB2 SB4 = SB_ON: Solder Bridge ON; Fitted: YES; Ordered_by: Subcon
SB3 = SB_ON: Solder Bridge ON; Ordered_by: Subcon
SB5 = SB_OFF: Solder Bridge OFF; Fitted: NO; Ordered_By: Subcon; Solder: NO
TP2 TP3 TP10 TP11 = TP 1mm: Test Point; Fitted: YES; Ordered_By: Subcon
U1-U4 = MP34DT01TR-M: MEMS audio sensor, omnidirectional digital microphone; Manuf_1: STM; Ordered_By: Subcon; Ref St: 9188008; ECCN_US/EU: EAR99/NEC; Fitted: YES
U6 U7 = 74LVC1G04SE: Single inverter gate with a standard push-pull output. (1.65V to 5.5V); Manuf_Part_1: 74LVC1G04SE-7; Manuf_1: DIODES INC; Order: 1845218; ECCN_US/EU: EAR99/NEC; Ordered_By: Subcon; Fitted: YES
U8 = WM8994ECS/R: Multi-Channel Audio Hub CODEC for Smartphones; Manuf_1: Cirrus Logic; ECCN_US/EU: EAR99/NEC; Fitted: YES; Ordered_By: Subcon

## Sheet Ethernet.SchDoc: Ethernet
size A4; Date: 01-DEC-2013; CompanyName: STMicroelectronics; Organization: Microcontrollers Division; Address1: 12, Rue Jules HOROWITZ; Address2: 38019 Grenoble; Address3: FRANCE; DocumentNumber: MB1262; Revision: C-01; SheetNumber: 14; SheetTotal: 17; Project: STM32MP15x-EVAL
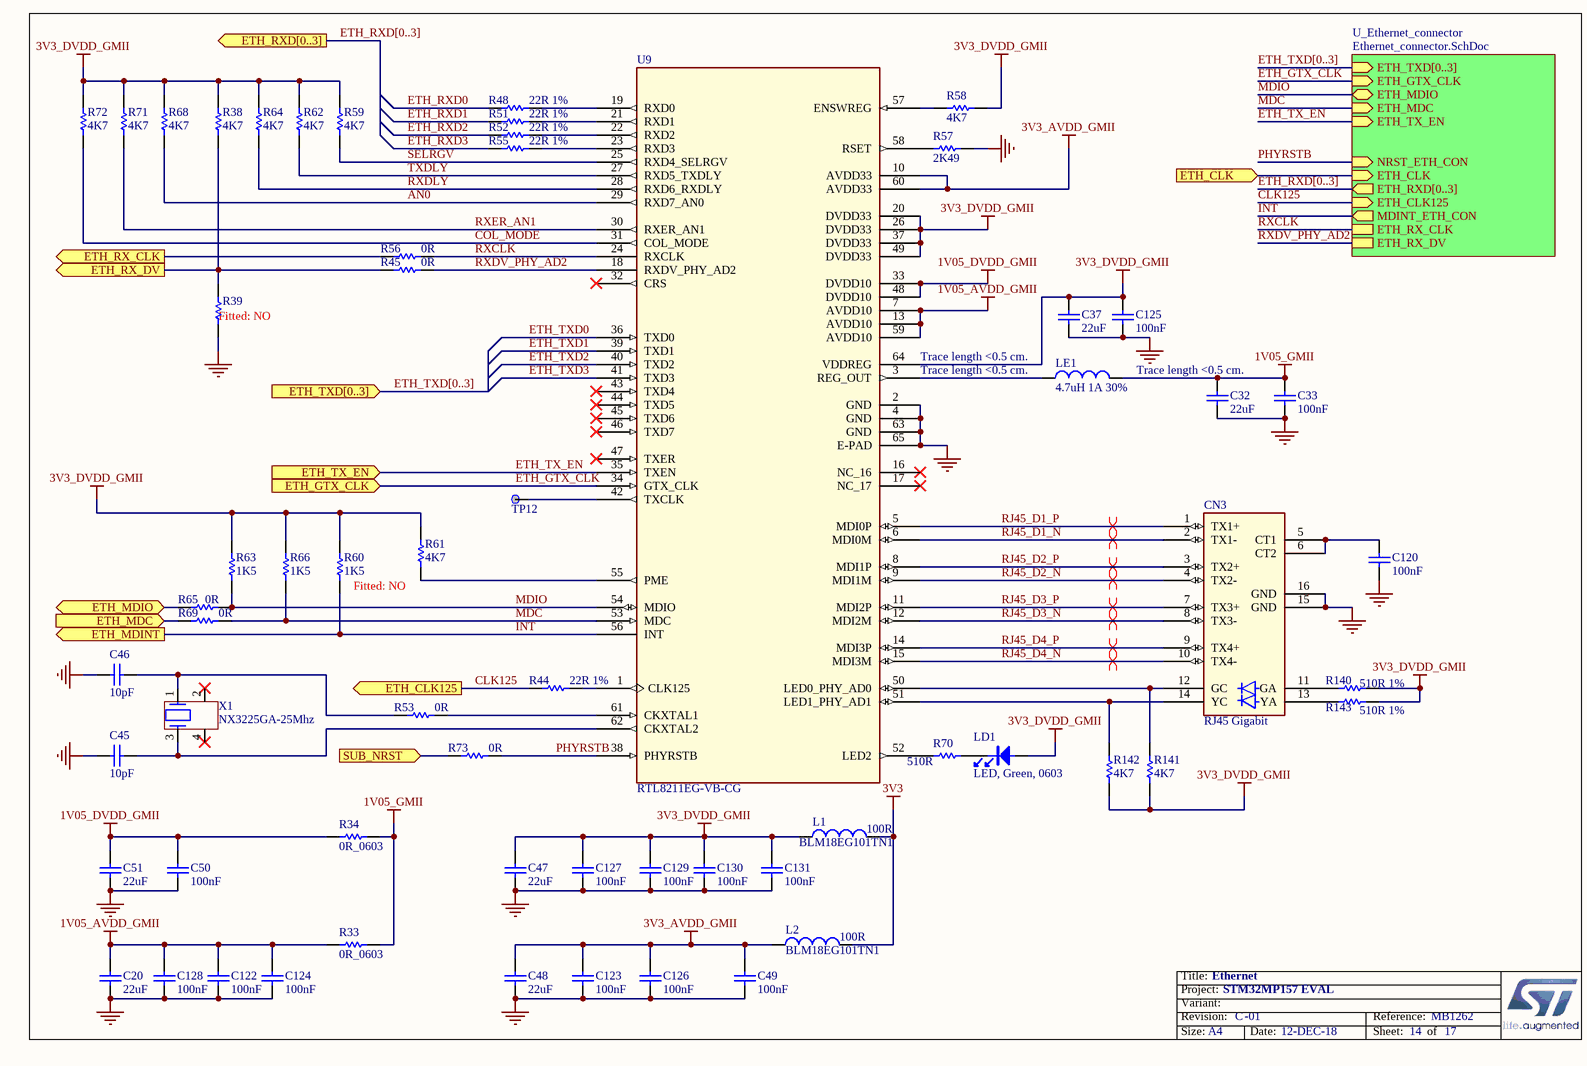
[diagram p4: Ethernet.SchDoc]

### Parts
C20  22uF  [C0805]
C32  22uF  [C0805]
C33  100nF  [C0402]
C37  22uF  [C0805]
C45  10pF  [C0402]
C46  10pF  [C0402]
C47  22uF  [C0805]
C48  22uF  [C0805]
C49  100nF  [C0402]
C50  100nF  [C0402]
C51  22uF  [C0805]
C120  100nF  [C0402]
C122  100nF  [C0402]
C123  100nF  [C0402]
C124  100nF  [C0402]
C125  100nF  [C0402]
C126  100nF  [C0402]
C127  100nF  [C0402]
C128  100nF  [C0402]
C129  100nF  [C0402]
C130  100nF  [C0402]
C131  100nF  [C0402]
CN3  RJ45 Gigabit  [CON_RJ45_YD_48F-01GYDXNL_LED-P]
L1  100R  Manuf_Part_1: BLM18EG101TN1  [L0603]
L2  100R  Manuf_Part_1: BLM18EG101TN1  [L0603]
LD1  LED, Green, 0603  [LED_0603_GREEN]
LE1  4.7uH 1A 30%  [L1210_LQH]
R33  0R_0603  [R0603]
R34  0R_0603  [R0603]
R38  4K7  [R0402]
R39  Fitted: NO  [R0402]  (hidden comment: 4K7)
R44  22R 1%  [R0402]
R45  0R  [R0402]
R48  22R 1%  [R0402]
R51  22R 1%  [R0402]
R52  22R 1%  [R0402]
R53  0R  [R0402]
R55  22R 1%  [R0402]
R56  0R  [R0402]
R57  2K49  [R0402]
R58  4K7  [R0402]
R59  4K7  [R0402]
R60  1K5  Fitted: NO  [R0402]
R61  4K7  [R0402]
R62  4K7  [R0402]
R63  1K5  [R0402]
R64  4K7  [R0402]
R65  0R  [R0402]
R66  1K5  [R0402]
R68  4K7  [R0402]
R69  0R  [R0402]
R70  510R  [R0402]
R71  4K7  [R0402]
R72  4K7  [R0402]
R73  0R  [R0402]
R140  510R 1%  [R0402]
R141  4K7  [R0402]
R142  4K7  [R0402]
R143  510R 1%  [R0402]
TP12  TP  [TP_SMD_1MM]  (value not drawn)
U9  RTL8211EG-VB-CG  [ICC_QFN64-EPAD_9X9_P050]
X1  NX3225GA-25Mhz  [CRY_NX3225HA_4P]

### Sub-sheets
U_Ethernet_connector = Ethernet_connector.SchDoc: ETH_TXD[0..3] (in), ETH_GTX_CLK (in), ETH_RX_DV, ETH_RX_CLK, ETH_MDIO (bidir), ETH_MDC (in), MDINT_ETH_CON (out), ETH_TX_EN (in), NRST_ETH_CON (in), ETH_RXD[0..3] (out), ETH_CLK (in), ETH_CLK125 (in)

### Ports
ETH_CLK125 (out), ETH_CLK (in), ETH_GTX_CLK (in), ETH_MDC (in), ETH_MDINT (out), ETH_MDIO (bidir), ETH_RX_CLK (out), ETH_RX_DV (out), ETH_RXD[0..3] (out), ETH_TX_EN (in), ETH_TXD[0..3] (in), SUB_NRST (in)

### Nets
1V05_AVDD_GMII: C20.2 C122.2 C124.2 C128.2 R33.1 U9.7(AVDD10) U9.13(AVDD10) U9.59(AVDD10)
1V05_DVDD_GMII: C50.2 C51.2 R34.1 U9.33(DVDD10) U9.48(DVDD10)
1V05_GMII: C32.2 C33.2 LE1.2 R33.2 R34.2
3V3: L1.2 L2.2
3V3_AVDD_GMII: C48.2 C49.2 C123.2 C126.2 L2.1 U9.10(AVDD33) U9.60(AVDD33)
3V3_DVDD_GMII: C37.2 C47.2 C125.2 C127.2 C129.2 C130.2 C131.2 L1.1 LD1.1 R38.2 R58.2 R59.2 R60.2 R61.2 R62.2 R63.2 R64.2 R66.2 R68.2 R71.2 R72.2 R140.2 R141.1 R142.1 R143.2 U9.20(DVDD33) U9.26(DVDD33) U9.37(DVDD33) U9.49(DVDD33) U9.64(VDDREG)
GND: C20.1 C32.1 C33.1 C37.1 C45.1 C46.1 C47.1 C48.1 C49.1 C50.1 C51.1 C120.1 C122.1 C123.1 C124.1 C125.1 C126.1 C127.1 C128.1 C129.1 C130.1 C131.1 CN3.15(GND) CN3.16(GND) R39.1 R57.1 U9.2(GND) U9.4(GND) U9.63(GND) U9.65(E-PAD)
AN0: R68.1 U9.29(RXD7_AN0)
CLK125: R44.1 ; port ETH_CLK125, sheet U_Ethernet_connector/ETH_CLK125
COL_MODE: R72.1 U9.31(COL_MODE)
ETH_GTX_CLK: U9.34(GTX_CLK) ; port ETH_GTX_CLK, sheet U_Ethernet_connector/ETH_GTX_CLK
ETH_MDC: R69.1 ; port ETH_MDC
ETH_MDIO: R65.1 ; port ETH_MDIO
ETH_RX_CLK: R56.1 ; port ETH_RX_CLK
ETH_RX_DV: R38.1 R39.2 R45.1 ; port ETH_RX_DV
ETH_RXD0: R48.1
ETH_RXD1: R51.1
ETH_RXD2: R52.1
ETH_RXD3: R55.1
ETH_TX_EN: U9.35(TXEN) ; port ETH_TX_EN, sheet U_Ethernet_connector/ETH_TX_EN
ETH_TXD0: U9.36(TXD0)
ETH_TXD1: U9.39(TXD1)
ETH_TXD2: U9.40(TXD2)
ETH_TXD3: U9.41(TXD3)
INT: R60.1 U9.56(INT) ; port ETH_MDINT, sheet U_Ethernet_connector/MDINT_ETH_CON  [project net ETH_MDINT]
MDC: R66.1 R69.2 U9.53(MDC) ; sheet U_Ethernet_connector/ETH_MDC
MDIO: R63.1 R65.2 U9.54(MDIO) ; sheet U_Ethernet_connector/ETH_MDIO
PHYRSTB: R73.2 U9.38(PHYRSTB) ; sheet U_Ethernet_connector/NRST_ETH_CON
RJ45_D1_N: CN3.2(TX1-) U9.6(MDI0M)
RJ45_D1_P: CN3.1(TX1+) U9.5(MDI0P)
RJ45_D2_N: CN3.4(TX2-) U9.9(MDI1M)
RJ45_D2_P: CN3.3(TX2+) U9.8(MDI1P)
RJ45_D3_N: CN3.8(TX3-) U9.12(MDI2M)
RJ45_D3_P: CN3.7(TX3+) U9.11(MDI2P)
RJ45_D4_N: CN3.10(TX4-) U9.15(MDI3M)
RJ45_D4_P: CN3.9(TX4+) U9.14(MDI3P)
RXCLK: R56.2 U9.24(RXCLK) ; sheet U_Ethernet_connector/ETH_RX_CLK
RXDLY: R64.1 U9.28(RXD6_RXDLY)
RXDV_PHY_AD2: R45.2 U9.18(RXDV_PHY_AD2) ; sheet U_Ethernet_connector/ETH_RX_DV
RXER_AN1: R71.1 U9.30(RXER_AN1)
SELRGV: R59.1 U9.25(RXD4_SELRGV)
TXDLY: R62.1 U9.27(RXD5_TXDLY)
NetC45_2: C45.2 U9.62(CKXTAL2) X1.3
NetC46_2: C46.2 R53.1 X1.1
NetC120_2: C120.2 CN3.5(CT1) CN3.6(CT2)
NetCN3_11: CN3.11(GA) R140.1
NetCN3_12: CN3.12(GC) R141.2 U9.50(LED0_PHY_AD0)
NetCN3_13: CN3.13(YA) R143.1
NetCN3_14: CN3.14(YC) R142.2 U9.51(LED1_PHY_AD1)
NetCN10_26: R73.1 ; port SUB_NRST
NetLD1_2: LD1.2 R70.2
NetLE1_1: LE1.1 U9.3(REG_OUT)
NetR44_2: R44.2 U9.1(CLK125)
NetR48_2: R48.2 U9.19(RXD0)
NetR51_2: R51.2 U9.21(RXD1)
NetR52_2: R52.2 U9.22(RXD2)
NetR53_2: R53.2 U9.61(CKXTAL1)
NetR55_2: R55.2 U9.23(RXD3)
NetR57_2: R57.2 U9.58(RSET)
NetR58_1: R58.1 U9.57(ENSWREG)
NetR61_1: R61.1 U9.55(PME)
NetR70_1: R70.1 U9.52(LED2)
NetR77_1: port ETH_CLK, sheet U_Ethernet_connector/ETH_CLK
NetTP12_1: TP12.1 U9.42(TXCLK)

Not connected (* = marked no-connect by the designer): U9 16(NC_16)* 17(NC_17)* 32(CRS)* 43(TXD4)* 44(TXD5)* 45(TXD6)* 46(TXD7)* 47(TXER)*; X1 2* 4*

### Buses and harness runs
bus ETH_RXD[0..3] = port ETH_RXD[0..3]
bus ETH_RXD[0..3] = sheet U_Ethernet_connector/ETH_RXD[0..3]
bus ETH_TXD[0..3] = port ETH_TXD[0..3]
bus ETH_TXD[0..3] = sheet U_Ethernet_connector/ETH_TXD[0..3]

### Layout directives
differential pair: RJ45_D1_N, RJ45_D1_P, RJ45_D2_N, RJ45_D2_P, RJ45_D3_N, RJ45_D3_P, RJ45_D4_N, RJ45_D4_P

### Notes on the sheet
- (near LE1) Trace length <0.5 cm.
- (near C32) Trace length <0.5 cm.

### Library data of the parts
C20 C32 C37 C47 C48 C51 = Cap_22uF_X5R_20%_0805: Capacitor,22uF,6.3V,X5R,20%,0805,Murata; Manuf_Part_1: GRM21BR60J226ME39L; Fitted: YES; Ordered_By: Subcon
C33 C49 C50 C120 C122-C131 = Cap_100nF_X7R_10%_0402: as C55 on sheet NAND
C45 C46 = Cap_10pF_NPO_5%_0402: Capacitor,10pF,50V,NPO,5%,0402,YAGEO; Order_Code: CC0402JRNPO9BN100; Fitted: YES; Ordered_By: subcon
CN3 = CON_RJ45_48F_01GYDXNL: RJ45 (shielded) Ethernet connector with Integral LEDs (green/yellow); Manuf_Part_1: 48F-01GYDXNL; Manuf_1: Yuan Dean Scientific Co Ltd; Fitted: YES; Ordered_By: Subcon
L1 L2 = BEAD_100R_2A_0603: Bead,100R at 100Mhz,2A,0603; Manuf_1: MURATA; Ordered_By: Subcon; Fitted: YES
LD1 = LED_green: Manuf_1: everlight; Manuf_Part_1: 19-213SYGC/S530-E2/TR8; ECCN_US/EU: EAR99/NEC; Fitted: YES; Ordered_By: Subcon
LE1 = Ind_4.7uH_1A_30%: FIXED IND 4.7UH 1A 180 MOHM 30% SMD; Manuf_Part_1: LQH32PN4R7NN0L; Manuf_1: MURATA; Order: 490-5338-1-ND; Ordered_By: Subcon; Fitted: YES
R33 R34 = Res_0_5%_0603: Resistor,0R,0603,5%,YAGEO; Manuf_Part_1: RC0603JR-070RL; Order_Code: 2363481; Fitted: YES; Ordered_By: subcon
R38 R58 R59 R61 R62 R64 R68 R71 R72 R141 R142 = Res_4K7_1%_0402: as R40 on sheet Audio
R39 = Res_4K7_1%_0402: Resistor,4K7,0402,1%,YAGEO; Manuf_Part_2: RT0402FRE074K7L; Manuf_Part_1: RC0402FR-074K7L; Ordered_By: Subcon
R44 R48 R51 R52 R55 = Res_22_1%_0402: Resistor,22R,0402,1%,YAGEO; Manuf_Part_1: RC0402FR-0722RL; Order_Code: 9239030RL; Fitted: YES; Ordered_By: Subcon
R45 R53 R56 R65 R69 R73 = Res_0_5%_0402: as R1 on sheet Audio
R57 = Res_2K49_1%_0402: Resistor,2K49,0402,1%,YAGEO; Manuf_Part_1: RC0402FR-072K49L; Fitted: YES; Ordered_By: Subcon
R60 = Res_1K5_1%_0402: Resistor,1K5,0402,1%,YAGEO; Manuf_Part_1: RC0402FR-071K5L; Ordered_By: Subcon
R63 R66 = Res_1K5_1%_0402: Resistor,1K5,0402,1%,YAGEO; Manuf_Part_1: RC0402FR-071K5L; Fitted: YES; Ordered_By: Subcon
R70 R140 R143 = Res_510_1%_0402: Resistor,510R,0402,1%,YAGEO; Manuf_Part_1: RC0402FR-07510RL; Order_Code: 1458804; Fitted: YES; Ordered_By: Subcon
TP12 = TP 1mm: as TP2 on sheet Audio
U9 = RTL8211EG: REALTEK 10/100/1000 GIGABIT Ethernet Transceiver; Fitted: YES; Ordered_By: Subcon
X1 = XTAL_25M_NX3225GA: Surface mount Crystal. Load capacitance: 10pF; Manuf_Part_1: NX3225GA 25MHz EXS00A-CG06750; Manuf_1: NDK; Fitted: Yes; Ordered_By: STM; Value: 25MHz

## Sheet Ethernet_connector.SchDoc: Ethernet_connector
size A4; Date: 01-DEC-2013; CompanyName: STMicroelectronics; Organization: Microcontrollers Division; Address1: 12, Rue Jules HOROWITZ; Address2: 38019 Grenoble; Address3: FRANCE; DocumentNumber: MB1262; Revision: C-01; SheetNumber: 15; SheetTotal: 17; Project: STM32MP15x-EVAL
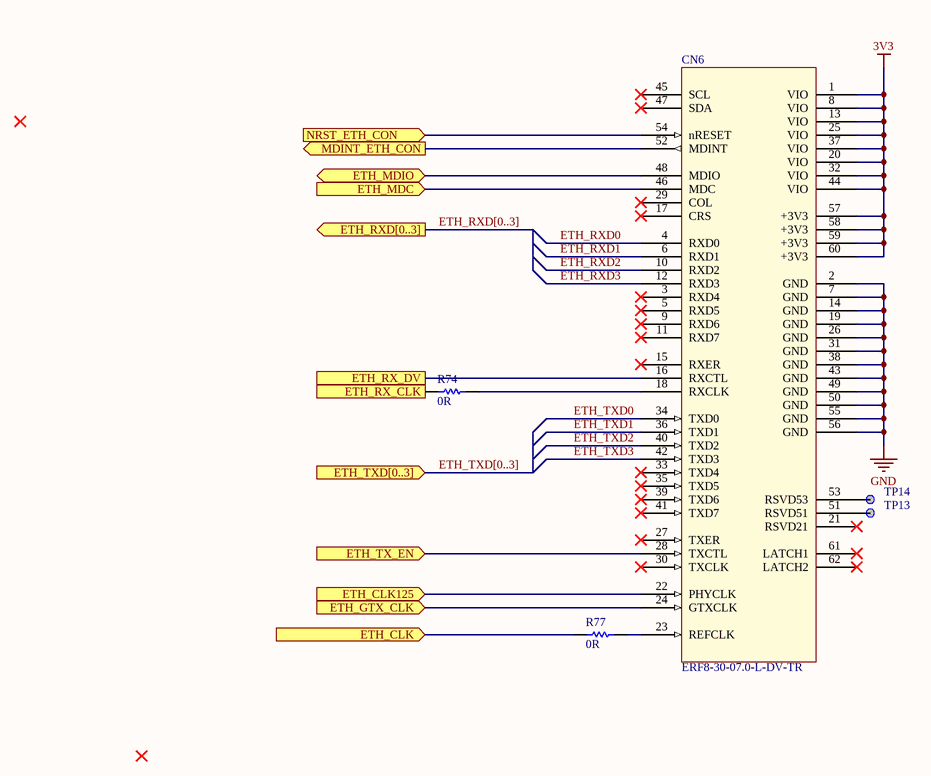
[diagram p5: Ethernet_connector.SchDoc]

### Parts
CN6  ERF8-30-07.0-L-DV-TR  [CON_SAMTEC_ERF8-030-070-L-DV-TR_MOD-B2123A]
R74  0R  [R0402]
R77  0R  [R0402]
TP13  TP  [TP_SMD_1MM]  (value not drawn)
TP14  TP  [TP_SMD_1MM]  (value not drawn)

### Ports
ETH_CLK125 (in), ETH_CLK (in), ETH_GTX_CLK (in), ETH_MDC (in), ETH_MDIO (bidir), ETH_RX_CLK, ETH_RX_DV, ETH_RXD[0..3] (out), ETH_TX_EN (in), ETH_TXD[0..3] (in), MDINT_ETH_CON (out), NRST_ETH_CON (in)

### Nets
3V3: CN6.1(VIO) CN6.8(VIO) CN6.13(VIO) CN6.20(VIO) CN6.25(VIO) CN6.32(VIO) CN6.37(VIO) CN6.44(VIO) CN6.57(+3V3) CN6.58(+3V3) CN6.59(+3V3) CN6.60(+3V3)
GND: CN6.2(GND) CN6.7(GND) CN6.14(GND) CN6.19(GND) CN6.26(GND) CN6.31(GND) CN6.38(GND) CN6.43(GND) CN6.49(GND) CN6.50(GND) CN6.55(GND) CN6.56(GND)
CLK125: CN6.22(PHYCLK) ; port ETH_CLK125
ETH_GTX_CLK: CN6.24(GTXCLK) ; port ETH_GTX_CLK
ETH_MDINT: CN6.52(MDINT) ; port MDINT_ETH_CON
ETH_RXD0: CN6.4(RXD0)
ETH_RXD1: CN6.6(RXD1)
ETH_RXD2: CN6.10(RXD2)
ETH_RXD3: CN6.12(RXD3)
ETH_TX_EN: CN6.28(TXCTL) ; port ETH_TX_EN
ETH_TXD0: CN6.34(TXD0)
ETH_TXD1: CN6.36(TXD1)
ETH_TXD2: CN6.40(TXD2)
ETH_TXD3: CN6.42(TXD3)
MDC: CN6.46(MDC) ; port ETH_MDC
MDIO: CN6.48(MDIO) ; port ETH_MDIO
PHYRSTB: CN6.54(nRESET) ; port NRST_ETH_CON
RXCLK: R74.1 ; port ETH_RX_CLK
RXDV_PHY_AD2: CN6.16(RXCTL) ; port ETH_RX_DV
NetCN6_18: CN6.18(RXCLK) R74.2
NetCN6_23: CN6.23(REFCLK) R77.2
NetCN6_51: CN6.51(RSVD51) TP13.1
NetCN6_53: CN6.53(RSVD53) TP14.1
NetR77_1: R77.1 ; port ETH_CLK

Not connected (* = marked no-connect by the designer): CN6 3(RXD4)* 5(RXD5)* 9(RXD6)* 11(RXD7)* 15(RXER)* 17(CRS)* 21(RSVD21)* 27(TXER)* 29(COL)* 30(TXCLK)* 33(TXD4)* 35(TXD5)* 39(TXD6)* 41(TXD7)* 45(SCL)* 47(SDA)* 61(LATCH1)* 62(LATCH2)*

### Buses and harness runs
bus ETH_RXD[0..3] = port ETH_RXD[0..3]
bus ETH_TXD[0..3] = port ETH_TXD[0..3]

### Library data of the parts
CN6 = CONN_ERF8_030: RJ45 (shielded) Ethernet connector with Integral LEDs (green/yellow); Manuf_1: SAMTEC; Fitted: YES; Ordered_By: Subcon
R74 R77 = Res_0_5%_0402: as R1 on sheet Audio
TP13 TP14 = TP 1mm: as TP2 on sheet Audio

## Sheet DSI&TFT-LCD&Camera.SchDoc: LTDC connectors & Camera
size A4; DocumentNumber: MB1262; Revision: C-01; SheetNumber: 12; SheetTotal: 17; Project: STM32MP15x-EVAL
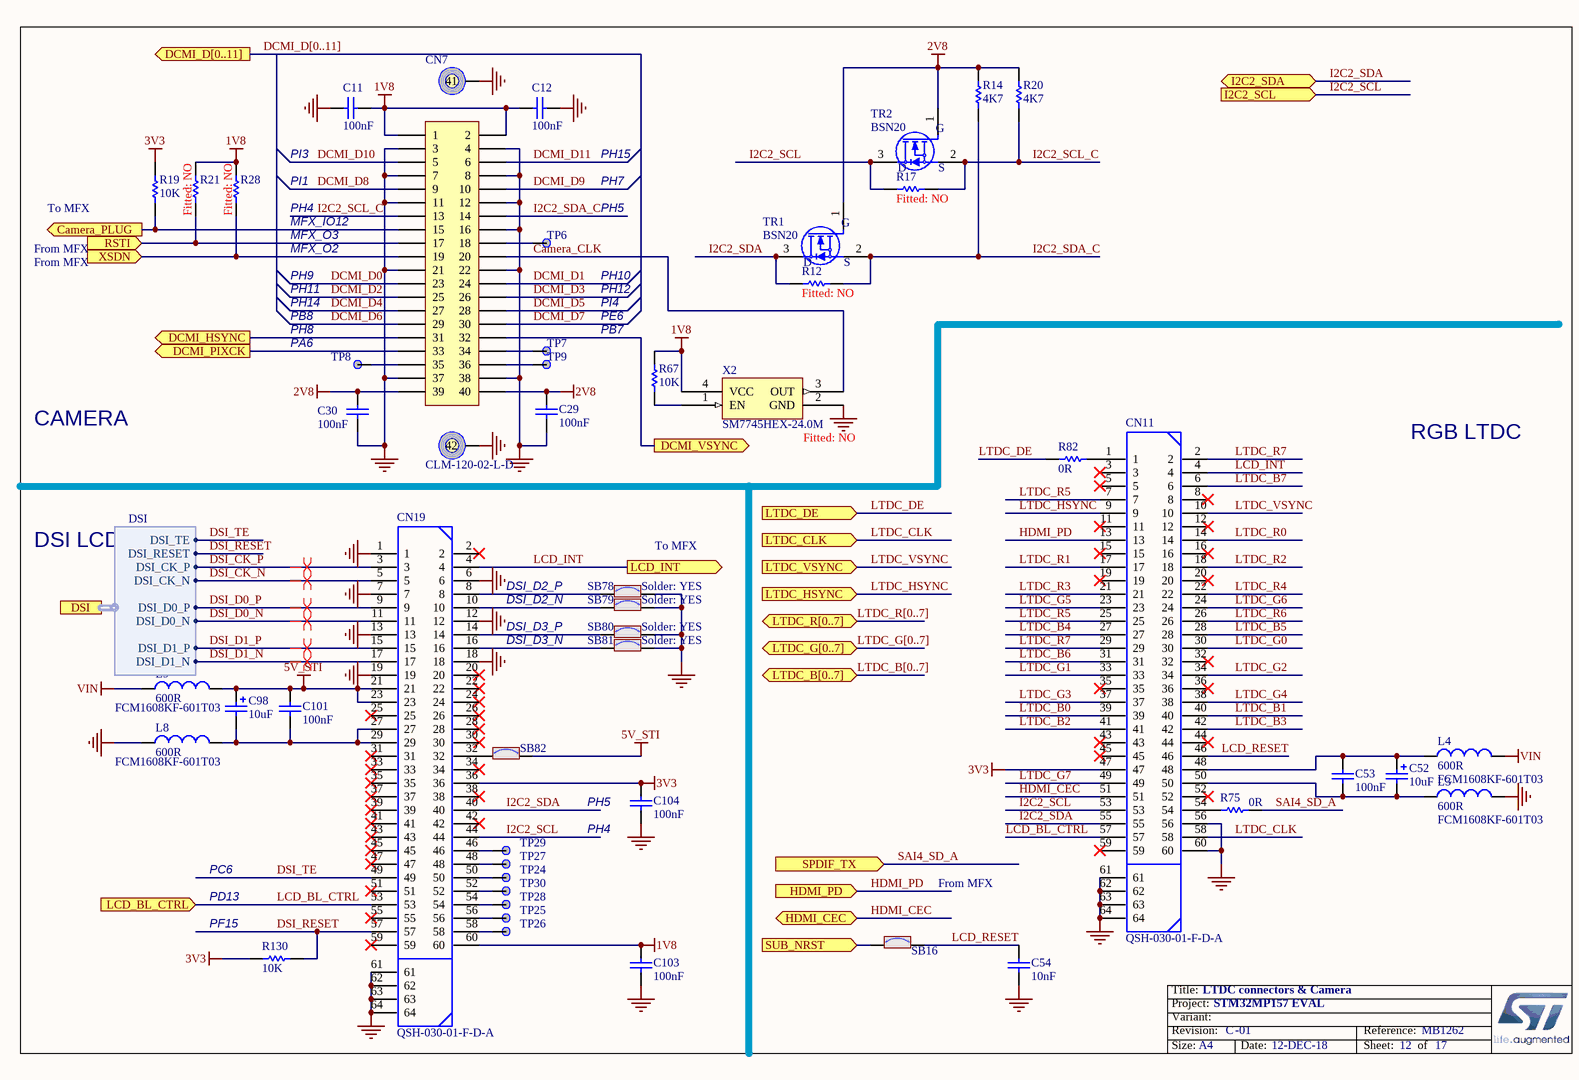
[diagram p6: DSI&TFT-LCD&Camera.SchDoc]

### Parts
C11  100nF  [C0402]
C12  100nF  [C0402]
C29  100nF  [C0402]
C30  100nF  [C0402]
C52  10uF  [CPOL_TAJ-A_1206_H180]
C53  100nF  [C0402]
C54  10nF  [C0402]
C98  10uF  [CPOL_TAJ-A_1206_H180]
C101  100nF  [C0402]
C103  100nF  [C0402]
C104  100nF  [C0402]
CN7  CLM-120-02-L-D  [CON_SAMTEC_CLM-120-02-L-D_Reverse-to-Camera]
CN11  QSH-030-01-F-D-A  [CON_SAMTEC_QSH-030-01-F-D-A]
CN19  QSH-030-01-F-D-A  [CON_SAMTEC_QSH-030-01-F-D-A_LCD-MB1230]
L3  600R  Manuf_Part_1: FCM1608KF-601T03  [L0603]
L4  600R  Manuf_Part_1: FCM1608KF-601T03  [L0603]
L8  600R  Manuf_Part_1: FCM1608KF-601T03  [L0603]
L9  600R  Manuf_Part_1: FCM1608KF-601T03  [L0603]
R12  Fitted: NO  [R0402]  (hidden comment: 1K)
R14  4K7  [R0402]
R17  Fitted: NO  [R0402]  (hidden comment: 1K)
R19  10K  [R0402]
R20  4K7  [R0402]
R21  Fitted: NO  [R0402]  (hidden comment: 1K)
R28  Fitted: NO  [R0402]  (hidden comment: 1K)
R67  10K  [R0402]
R75  0R  [R0402]
R82  0R  [R0402]
R130  10K  [R0402]
SB16  SB_ON  [SOLDER-BRIDGE_R0603-0R]  (value not drawn)
SB78  Solder: YES  [SOLDER-BRIDGE_R0603-0R]  (hidden comment: SB_ON)
SB79  Solder: YES  [SOLDER-BRIDGE_R0603-0R]  (hidden comment: SB_ON)
SB80  Solder: YES  [SOLDER-BRIDGE_R0603-0R]  (hidden comment: SB_ON)
SB81  Solder: YES  [SOLDER-BRIDGE_R0603-0R]  (hidden comment: SB_ON)
SB82  SB_ON  [SOLDER-BRIDGE_R0603-0R]  (value not drawn)
TP6  TP  [TP_SMD_1MM]  (value not drawn)
TP7  TP  [TP_SMD_1MM]  (value not drawn)
TP8  TP  [TP_SMD_1MM]  (value not drawn)
TP9  TP  [TP_SMD_1MM]  (value not drawn)
TP24  TP  [TP_SMD_1MM]  (value not drawn)
TP25  TP  [TP_SMD_1MM]  (value not drawn)
TP26  TP  [TP_SMD_1MM]  (value not drawn)
TP27  TP  [TP_SMD_1MM]  (value not drawn)
TP28  TP  [TP_SMD_1MM]  (value not drawn)
TP29  TP  [TP_SMD_1MM]  (value not drawn)
TP30  TP  [TP_SMD_1MM]  (value not drawn)
TR1  BSN20  [MOS_SOT23]
TR2  BSN20  [MOS_SOT23]
X2  SM7745HEX-24.0M  Fitted: NO  [OSC_PLE_SM77H-SERIES_7X5_H1P73_4P]

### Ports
Camera_PLUG (out), DCMI_D[0..11] (out), DCMI_HSYNC (out), DCMI_PIXCK (out), DCMI_VSYNC (out), DSI (harness DSI), HDMI_CEC (bidir), HDMI_PD (in), I2C2_SCL (in), I2C2_SDA (bidir), LCD_BL_CTRL (in), LCD_INT (out), LTDC_B[0..7] (bidir), LTDC_CLK (in), LTDC_DE (in), LTDC_G[0..7] (bidir), LTDC_HSYNC (in), LTDC_R[0..7] (bidir), LTDC_VSYNC (in), RSTI (in), SPDIF_TX (in), SUB_NRST (in), XSDN (in)

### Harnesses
DSI: DSI_CK_P, DSI_CK_N, DSI_D0_P, DSI_D0_N, DSI_D1_P, DSI_D1_N, DSI_TE, DSI_RESET

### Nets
1V8: C11.1 C12.2 C103.2 CN7.1 CN7.2 CN19.60 R21.1 R28.1 R67.2 X2.4(VCC)
2V8: C29.1 C30.1 CN7.39 CN7.40 R14.2 R20.2 TR1.1(G) TR2.1(G)
3V3: C104.2 CN11.47 CN19.36 R19.2 R130.1
5V_STI: C98.1 C101.2 CN19.21 CN19.23 L9.2 SB82.2
GND: C11.2 C12.1 C29.2 C30.2 C54.1 C103.1 C104.1 CN7.3 CN7.4 CN7.7 CN7.8 CN7.11 CN7.12 CN7.16 CN7.21 CN7.22 CN7.37 CN7.38 CN7.41 CN7.42 CN11.56 CN11.60 CN11.61 CN11.62 CN11.63 CN11.64 CN19.1 CN19.6 CN19.7 CN19.12 CN19.13 CN19.18 CN19.19 CN19.61 CN19.62 CN19.63 CN19.64 L3.2 L8.1 SB78.2 SB79.2 SB80.2 SB81.2 X2.2(GND)
VIN: L4.2 L9.1
Camera_CLK: CN7.20 X2.3(OUT)
DCMI_D0: CN7.23
DCMI_D1: CN7.24
DCMI_D2: CN7.25
DCMI_D3: CN7.26
DCMI_D4: CN7.27
DCMI_D5: CN7.28
DCMI_D6: CN7.29
DCMI_D7: CN7.30
DCMI_D8: CN7.9
DCMI_D9: CN7.10
DCMI_D10: CN7.5
DCMI_D11: CN7.6
DCMI_HSYNC: CN7.31 ; port DCMI_HSYNC
DCMI_PIXCK: CN7.33 ; port DCMI_PIXCK
DCMI_VSYNC: CN7.32 ; port DCMI_VSYNC
DSI_CK_N: CN19.5 ; port DSI.DSI_CK_N
DSI_CK_P: CN19.3 ; port DSI.DSI_CK_P
DSI_D0_N: CN19.11 ; port DSI.DSI_D0_N
DSI_D0_P: CN19.9 ; port DSI.DSI_D0_P
DSI_D1_N: CN19.17 ; port DSI.DSI_D1_N
DSI_D1_P: CN19.15 ; port DSI.DSI_D1_P
DSI_RESET: CN19.57 R130.2 ; port DSI.DSI_RESET
DSI_TE: CN19.49 ; port DSI.DSI_TE
HDMI_CEC: CN11.51 ; port HDMI_CEC
HDMI_PD: CN11.13 ; port HDMI_PD
I2C2_SCL: CN11.53 CN19.44 R17.1 TR2.3(D) ; port I2C2_SCL
I2C2_SCL_C: CN7.13 R17.2 R20.1 TR2.2(S)
I2C2_SDA: CN11.55 CN19.40 R12.1 TR1.3(D) ; port I2C2_SDA
I2C2_SDA_C: CN7.14 R12.2 R14.1 TR1.2(S)
LCD_BL_CTRL: CN11.57 CN19.53 ; port LCD_BL_CTRL
LCD_INT: CN11.4 CN19.4 ; port LCD_INT
LCD_RESET: C54.2 CN11.46 SB16.2
LTDC_B0: CN11.39
LTDC_B1: CN11.40
LTDC_B2: CN11.41
LTDC_B3: CN11.42
LTDC_B4: CN11.27
LTDC_B5: CN11.28
LTDC_B6: CN11.31
LTDC_B7: CN11.6
LTDC_CLK: CN11.58 ; port LTDC_CLK
LTDC_DE: R82.2 ; port LTDC_DE
LTDC_G0: CN11.30
LTDC_G1: CN11.33
LTDC_G2: CN11.34
LTDC_G3: CN11.37
LTDC_G4: CN11.38
LTDC_G5: CN11.23
LTDC_G6: CN11.24
LTDC_G7: CN11.49
LTDC_HSYNC: CN11.9 ; port LTDC_HSYNC
LTDC_R0: CN11.14
LTDC_R1: CN11.17
LTDC_R2: CN11.18
LTDC_R3: CN11.21
LTDC_R4: CN11.22
LTDC_R5: CN11.7 CN11.25
LTDC_R6: CN11.26
LTDC_R7: CN11.2 CN11.29
LTDC_VSYNC: CN11.10 ; port LTDC_VSYNC
SAI4_SD_A: R75.1 ; port SPDIF_TX
NetC52_1: C52.1 C53.2 CN11.48 L4.1
NetC52_2: C52.2 C53.1 CN11.50 L3.1
NetC98_2: C98.2 C101.1 CN19.27 CN19.29 L8.2
NetCN7_15: CN7.15 R19.1 ; port Camera_PLUG
NetCN7_17: CN7.17 R21.2 ; port RSTI
NetCN7_18: CN7.18 TP6.1
NetCN7_19: CN7.19 R28.2 ; port XSDN
NetCN7_34: CN7.34 TP7.1
NetCN7_35: CN7.35 TP8.1
NetCN7_36: CN7.36 TP9.1
NetCN10_26: SB16.1 ; port SUB_NRST
NetCN11_1: CN11.1 R82.1
NetCN11_54: CN11.54 R75.2
NetCN19_8: CN19.8 SB78.1
NetCN19_10: CN19.10 SB79.1
NetCN19_14: CN19.14 SB80.1
NetCN19_16: CN19.16 SB81.1
NetCN19_32: CN19.32 SB82.1
NetCN19_46: CN19.46 TP29.1
NetCN19_48: CN19.48 TP27.1
NetCN19_50: CN19.50 TP24.1
NetCN19_52: CN19.52 TP30.1
NetCN19_54: CN19.54 TP28.1
NetCN19_56: CN19.56 TP25.1
NetCN19_58: CN19.58 TP26.1
NetR67_1: R67.1 X2.1(EN)

Not connected (* = marked no-connect by the designer): CN11 3* 5* 8* 11* 12* 15* 16* 19* 20* 32* 35* 36* 43* 44* 45* 52* 59*; CN19 2* 20* 22* 24* 25* 26* 28* 30* 31* 33* 34* 35* 37* 38* 39* 41* 42* 43* 45* 47* 51* 55* 59*

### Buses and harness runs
bus DCMI_D[0..11] = port DCMI_D[0..11]
bus LTDC_B[0..7] = port LTDC_B[0..7]
bus LTDC_G[0..7] = port LTDC_G[0..7]
bus LTDC_R[0..7] = port LTDC_R[0..7]

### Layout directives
differential pair: DSI_CK_N, DSI_CK_P, DSI_D0_N, DSI_D0_P, DSI_D1_N, DSI_D1_P

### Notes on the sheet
- PI1
- PI3
- PH15
- PH7
- From MFX
- To MFX
- PH4
- MFX_IO12
- MFX_O3
- MFX_O2
- PH5
- PH14
- PB8
- PH8
- PH9
- PH11
- PE6
- PH10
- PH12
- PB7
- PI4
- PA6
- CAMERA
- RGB LTDC
- DSI LCD
- DSI_D2_P
- DSI_D2_N
- DSI_D3_P
- DSI_D3_N
- (near C104) PH5
- PC6
- (near C104) PH4
- PD13
- (near R130) PF15

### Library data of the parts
C11 C12 C29 C30 C53 C101 C103 C104 = Cap_100nF_X7R_10%_0402: as C55 on sheet NAND
C52 C98 = Cap_10uF_POL_10%_16V_1206: Polarized Capacitor,10uF,16V,10%,typeA,AVX; Manuf_Part_1: TAJA106K016R; Ordered_By: Subcon; Fitted: YES
C54 = Cap_10nF_X7R_10%_0402: Capacitor,10nF,16V,X7R,10%,0402,YAGEO; Manuf_Part_1: CC0402KRX7R7BB103; Fitted: YES; Ordered_By: Subcon
CN7 = CLM-120-02-L-D_2_Reverse_for_camera: Header, 20-Pin, Dual row; Manuf_1: SAMTEC; Order_Code: 1667554; Fitted: YES; Ordered_By: Subcon
CN11 = QSH-030-01-F-D-A: HIGH SPEED SOCKET STRIP, .5mm PITCH, 60 PINS; Manuf_1: SAMTEC; Fitted: YES; Ordered_By: Subcon
CN19 = QSH-030-01-F-D-A_DSI_LCD: HIGH SPEED SOCKET STRIP, .5mm PITCH, 60 PINS; Manuf_1: SAMTEC; Fitted: YES; Ordered_By: Subcon
L3 L4 L8 L9 = BEAD_600R_350MA_0603: Bead,600R,350mA,0603; Manuf_2: TDK; Manuf_Part_2: MPZ1608S300A; Manuf_1: Tai-tech; Manuf_Part_3: BLM18PG121SN1D; Manuf_3: MURATA; Ordered_By: Subcon; Fitted: YES
R12 R17 R21 R28 = Res_1K_1%_0402: Resistor,1K,0402,1%,YAGEO; Manuf_Part_1: RC0402FR-071KL; Ordered_By: Subcon
R14 R20 = Res_4K7_1%_0402: as R40 on sheet Audio
R19 R67 R130 = Res_10K_1%_0402: as R84 on sheet NAND
R75 R82 = Res_0_5%_0402: as R1 on sheet Audio
SB16 SB82 = SB_ON: as SB2 on sheet Audio
SB78-SB81 = SB_ON: Solder Bridge ON; Ordered_by: Subcon
TP6-TP9 TP24-TP30 = TP 1mm: as TP2 on sheet Audio
TR1 TR2 = BSN20: N-channel enhancement mode field-effect transistor; Manuf_1: NXP; Manuf_2: DiodesINc; Manuf_Part_2: BSN20-7; Fitted: YES; Ordered_By: Subcon
X2 = SM7745HEV-24.0M: SM77H Series 3.3V  CMOS Clock Oscillators; Manuf_1: Pletronics; Ordered_By: Subcon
